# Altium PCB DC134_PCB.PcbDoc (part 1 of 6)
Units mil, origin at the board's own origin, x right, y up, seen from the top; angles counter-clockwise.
Board outline 4000 x 2750 mil, 6 copper layers (L1_Top Layer, L2_GND1, L3_Signal, L4_Plane, L5_GND2, L6_Bottom Layer), stack 57.7 mil thick; 399 components, 238 nets, 1523 pads, 671 vias.
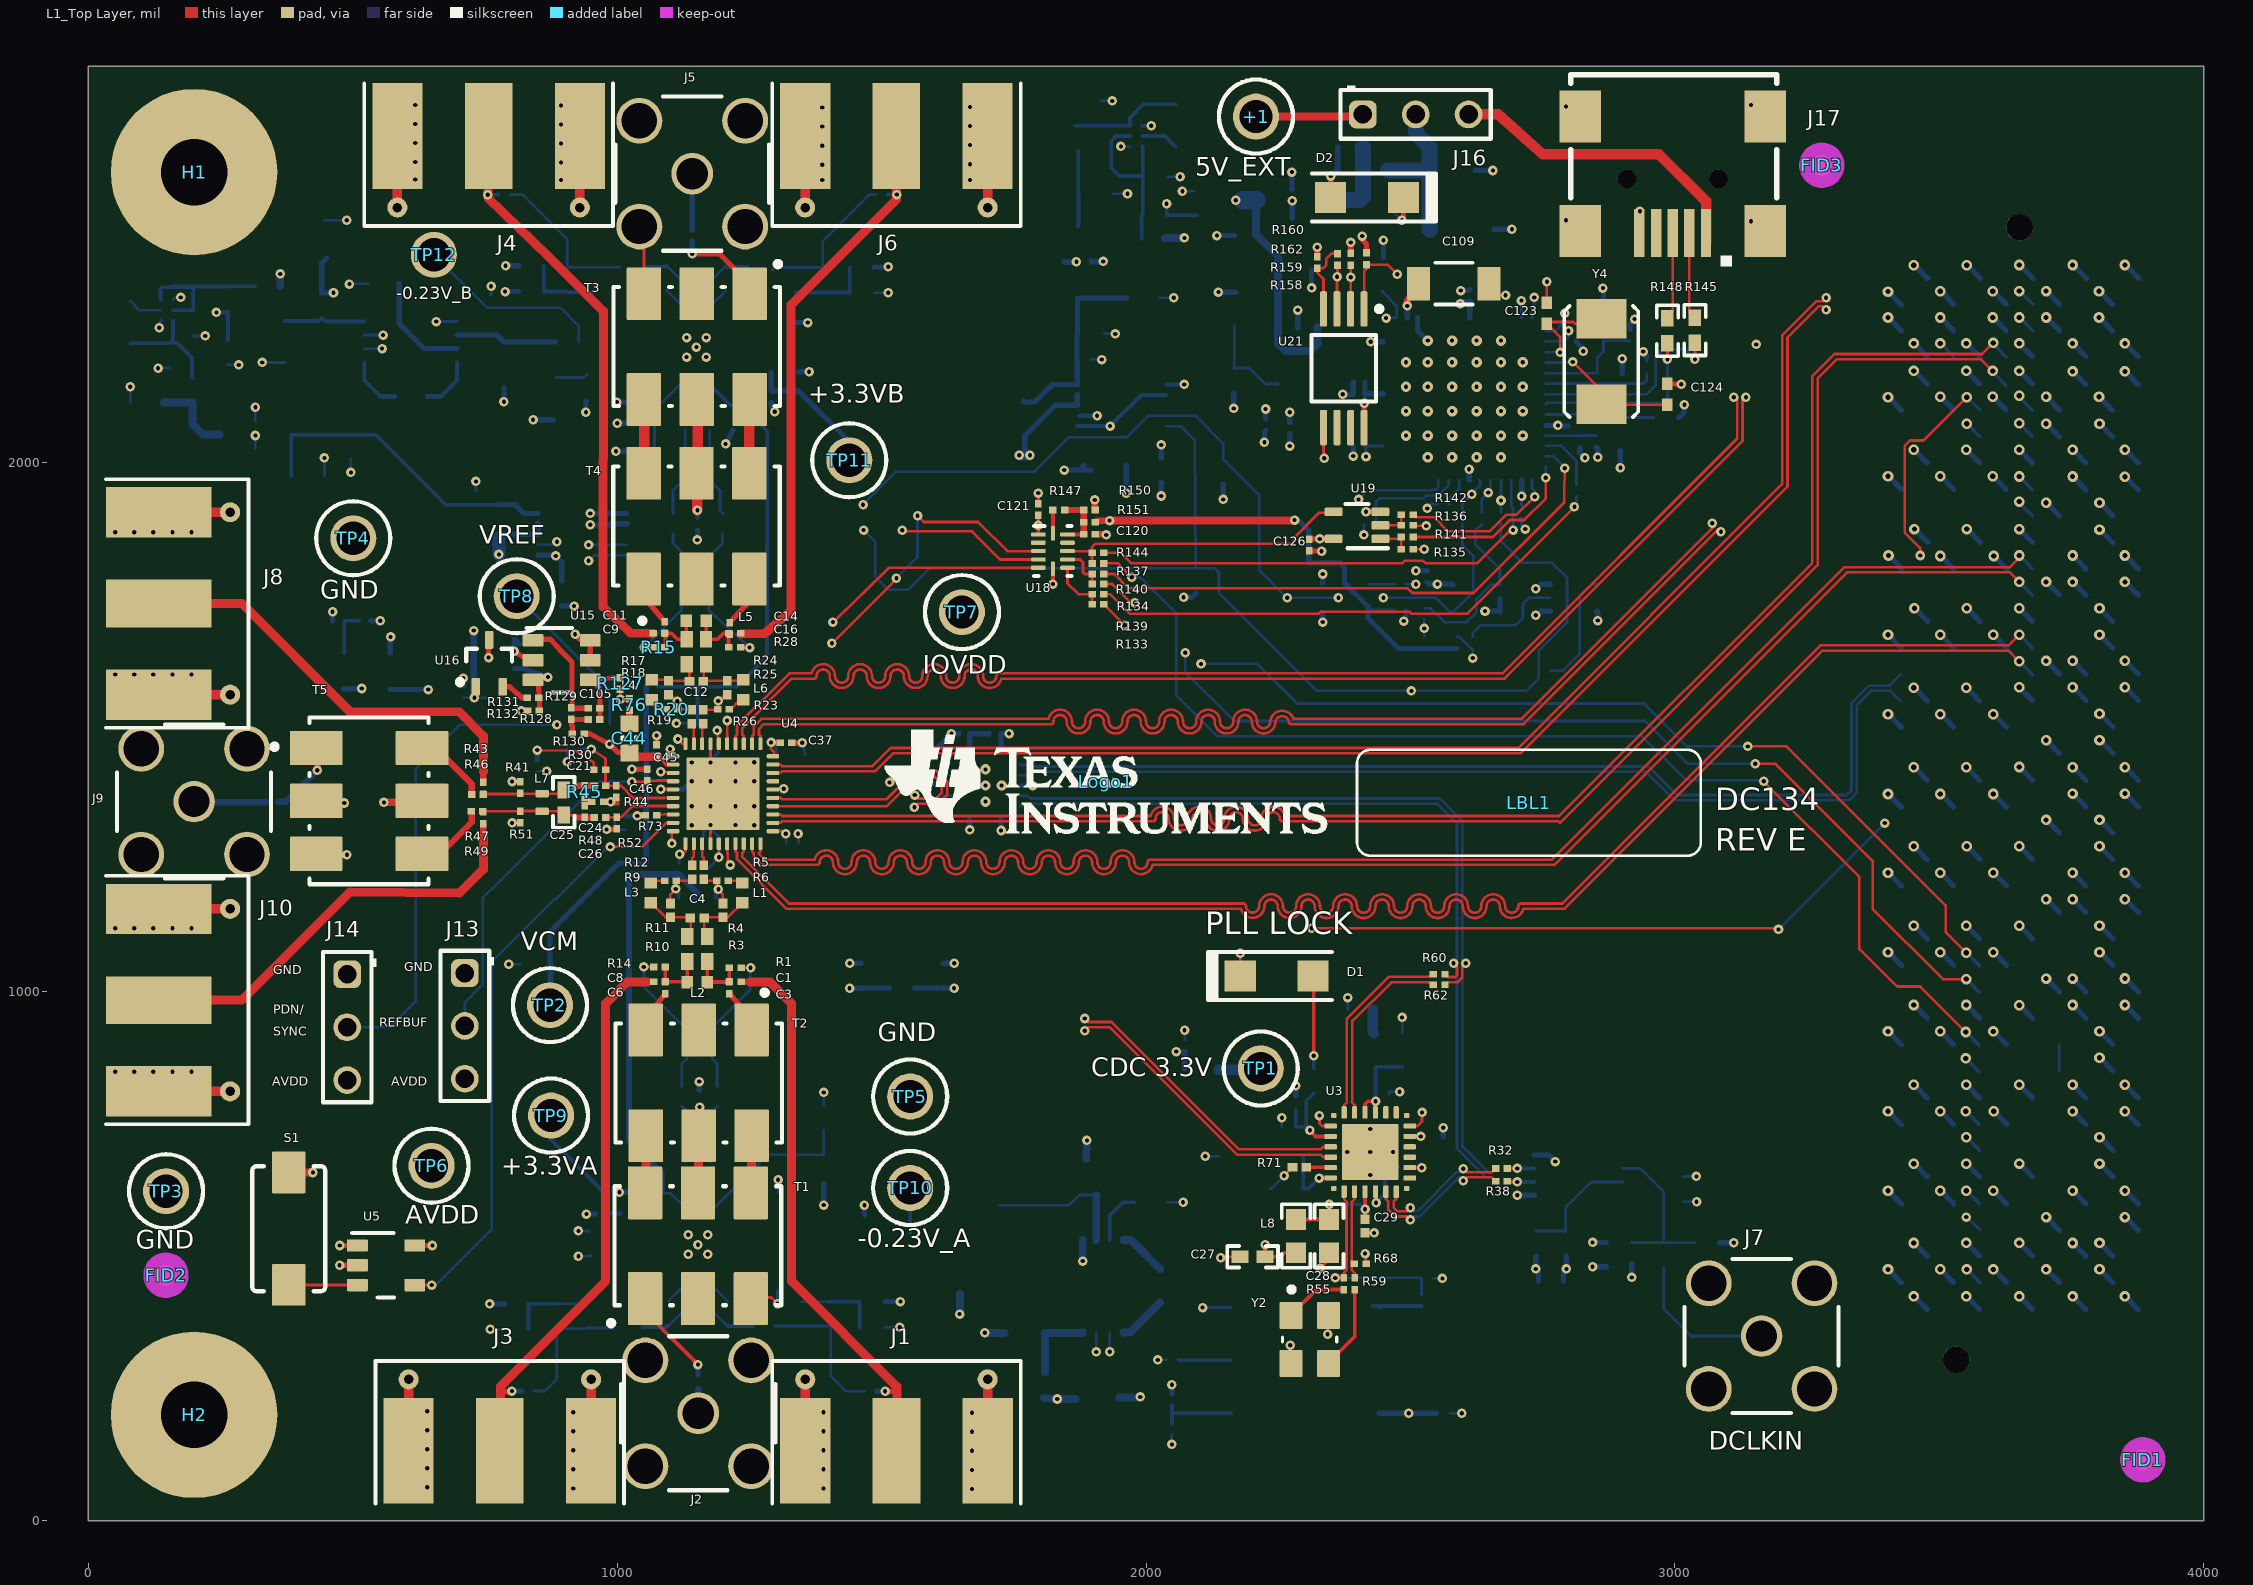
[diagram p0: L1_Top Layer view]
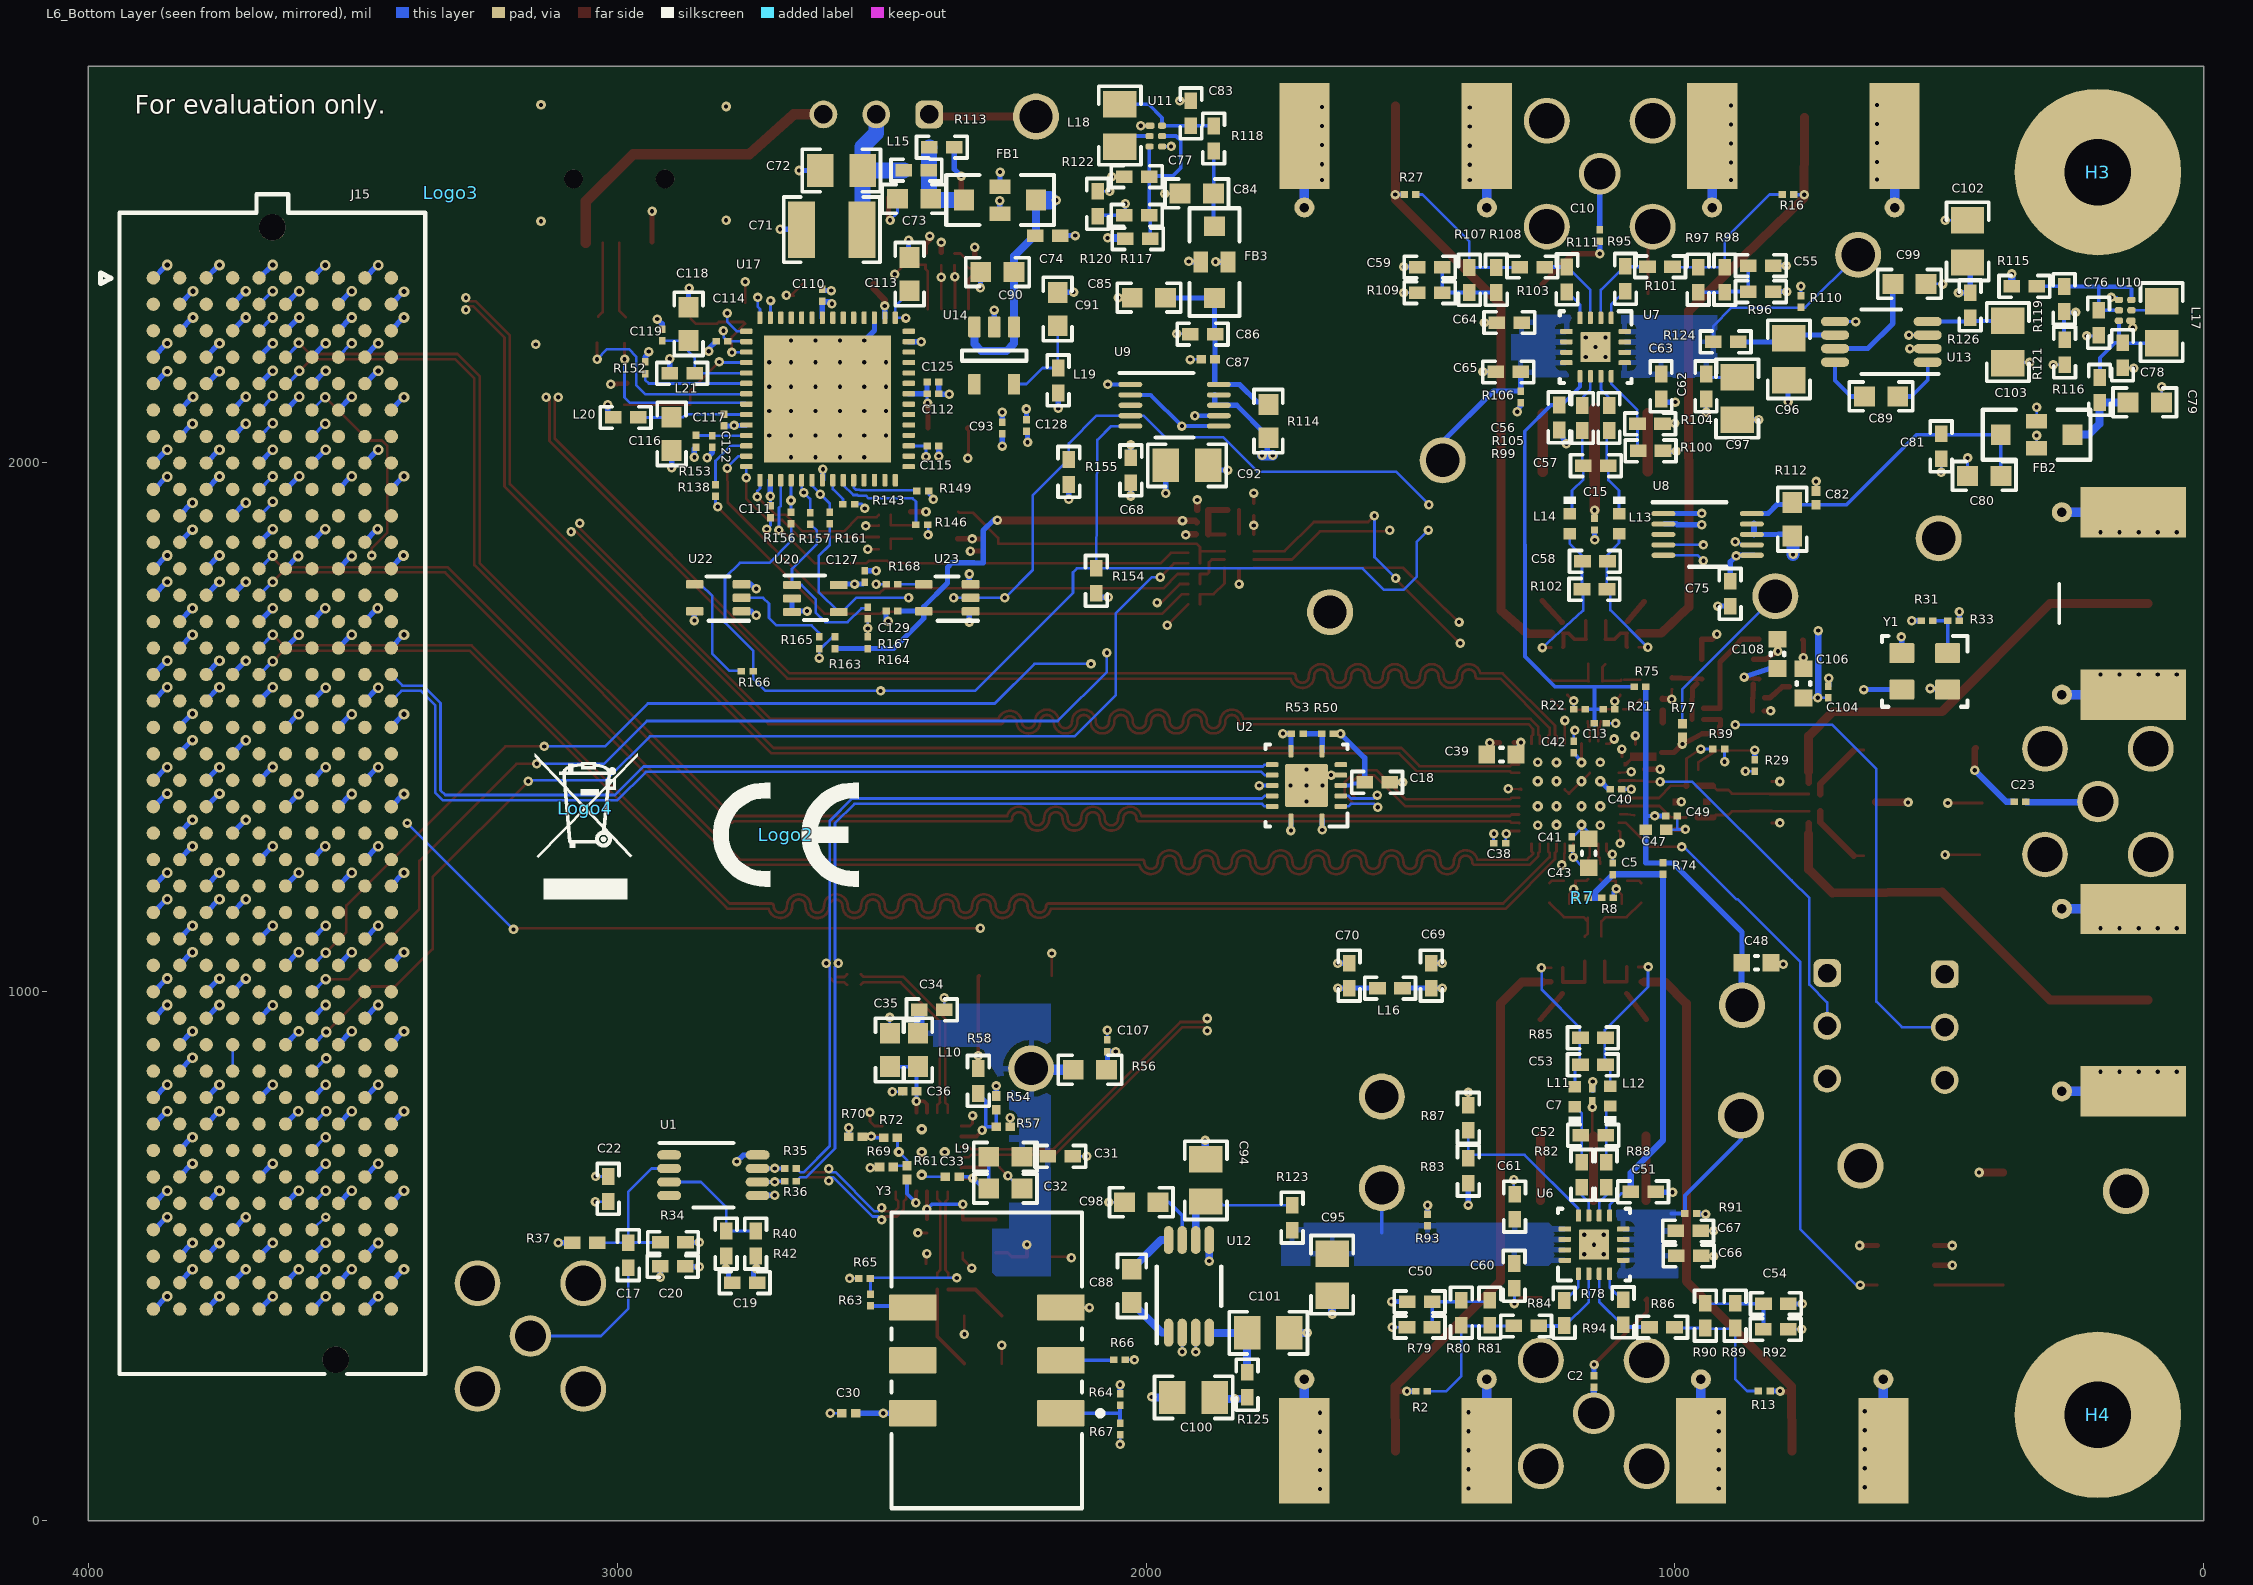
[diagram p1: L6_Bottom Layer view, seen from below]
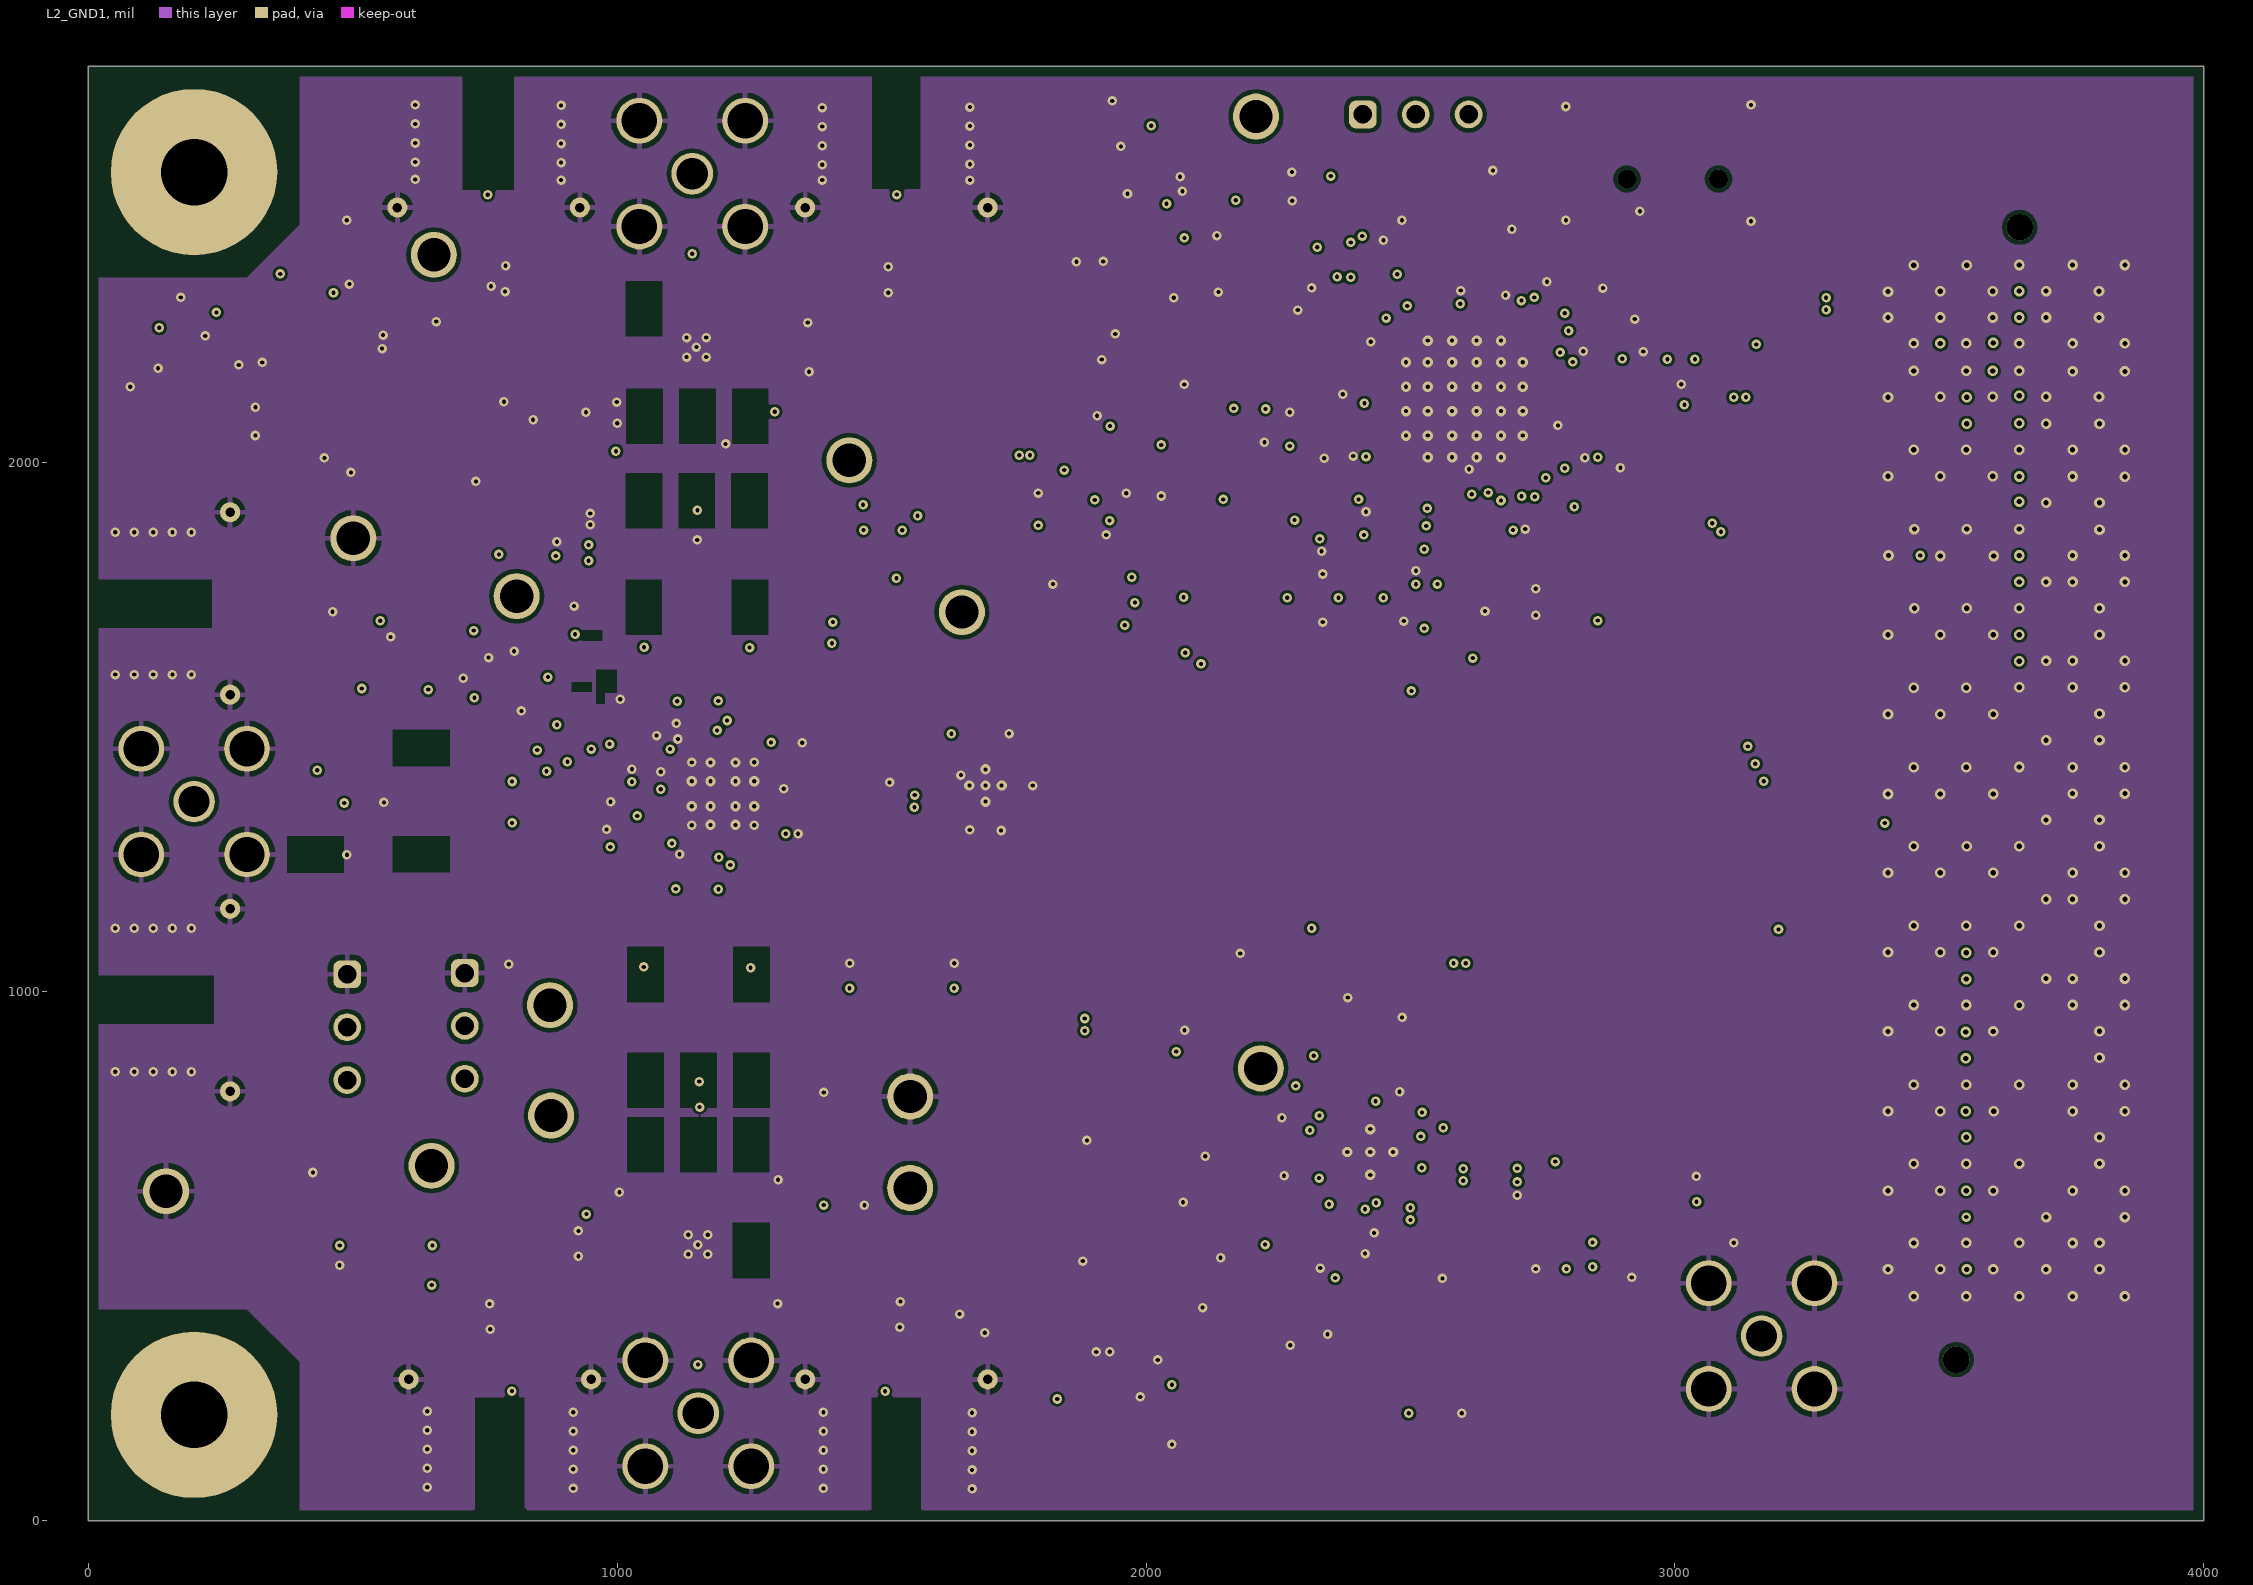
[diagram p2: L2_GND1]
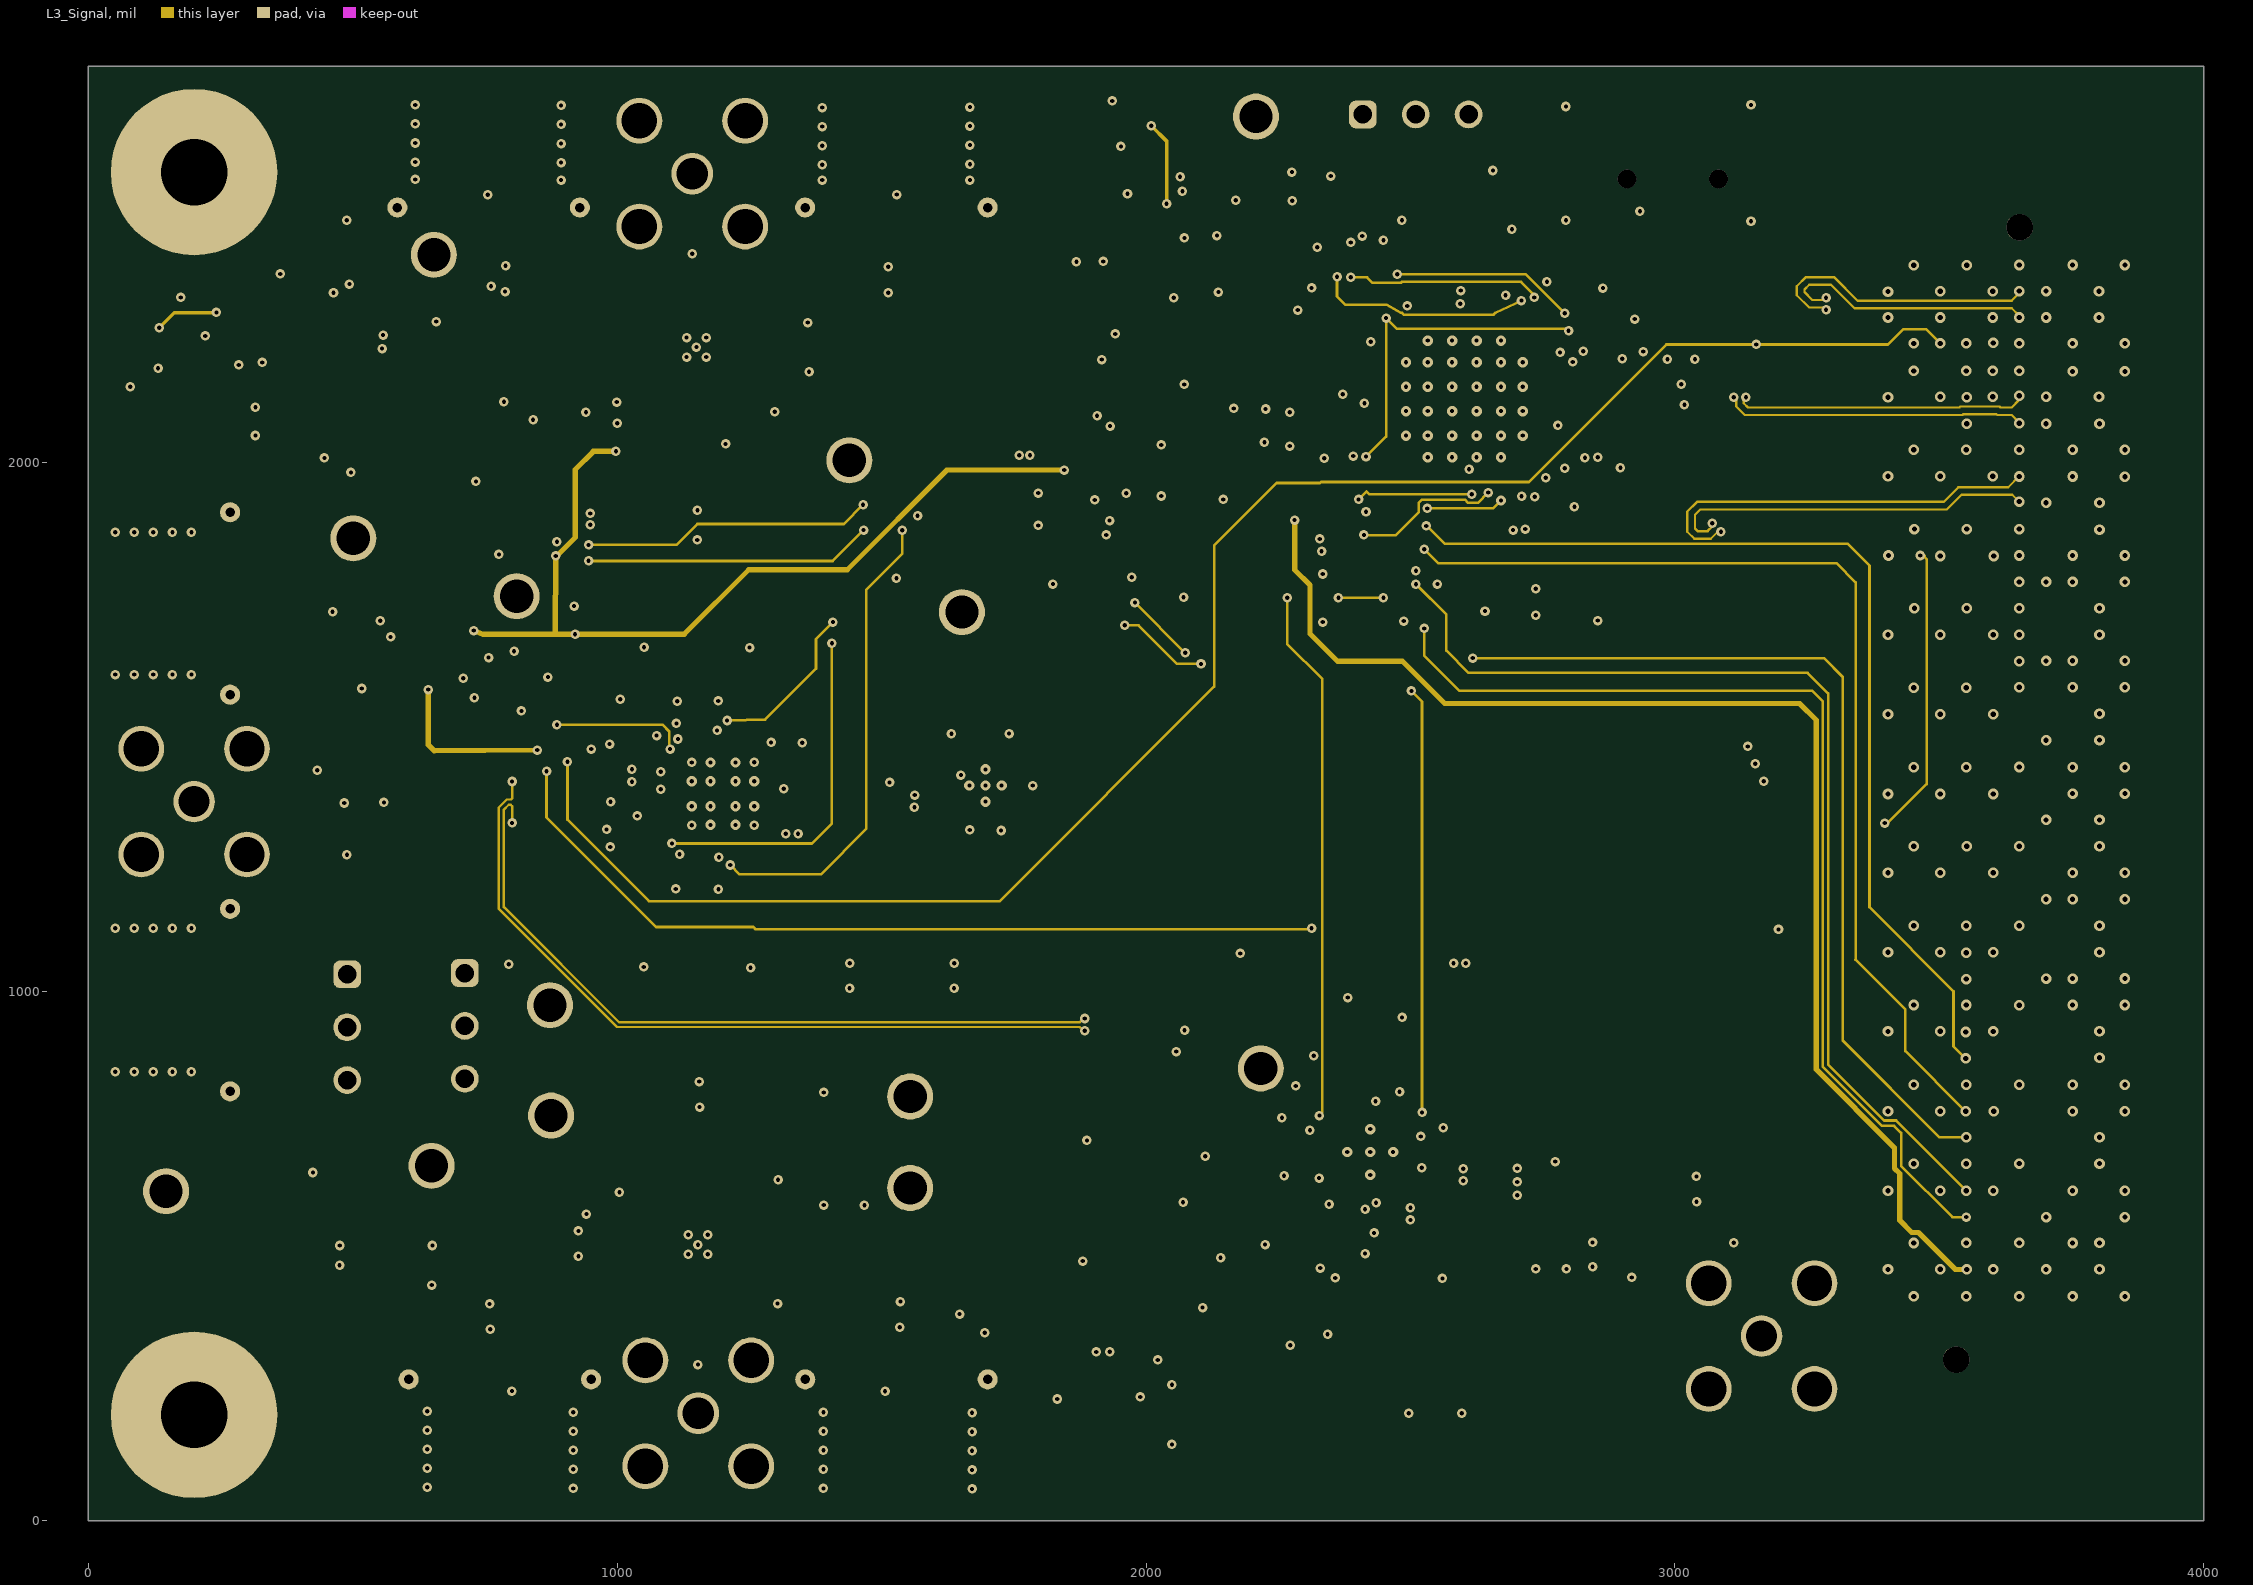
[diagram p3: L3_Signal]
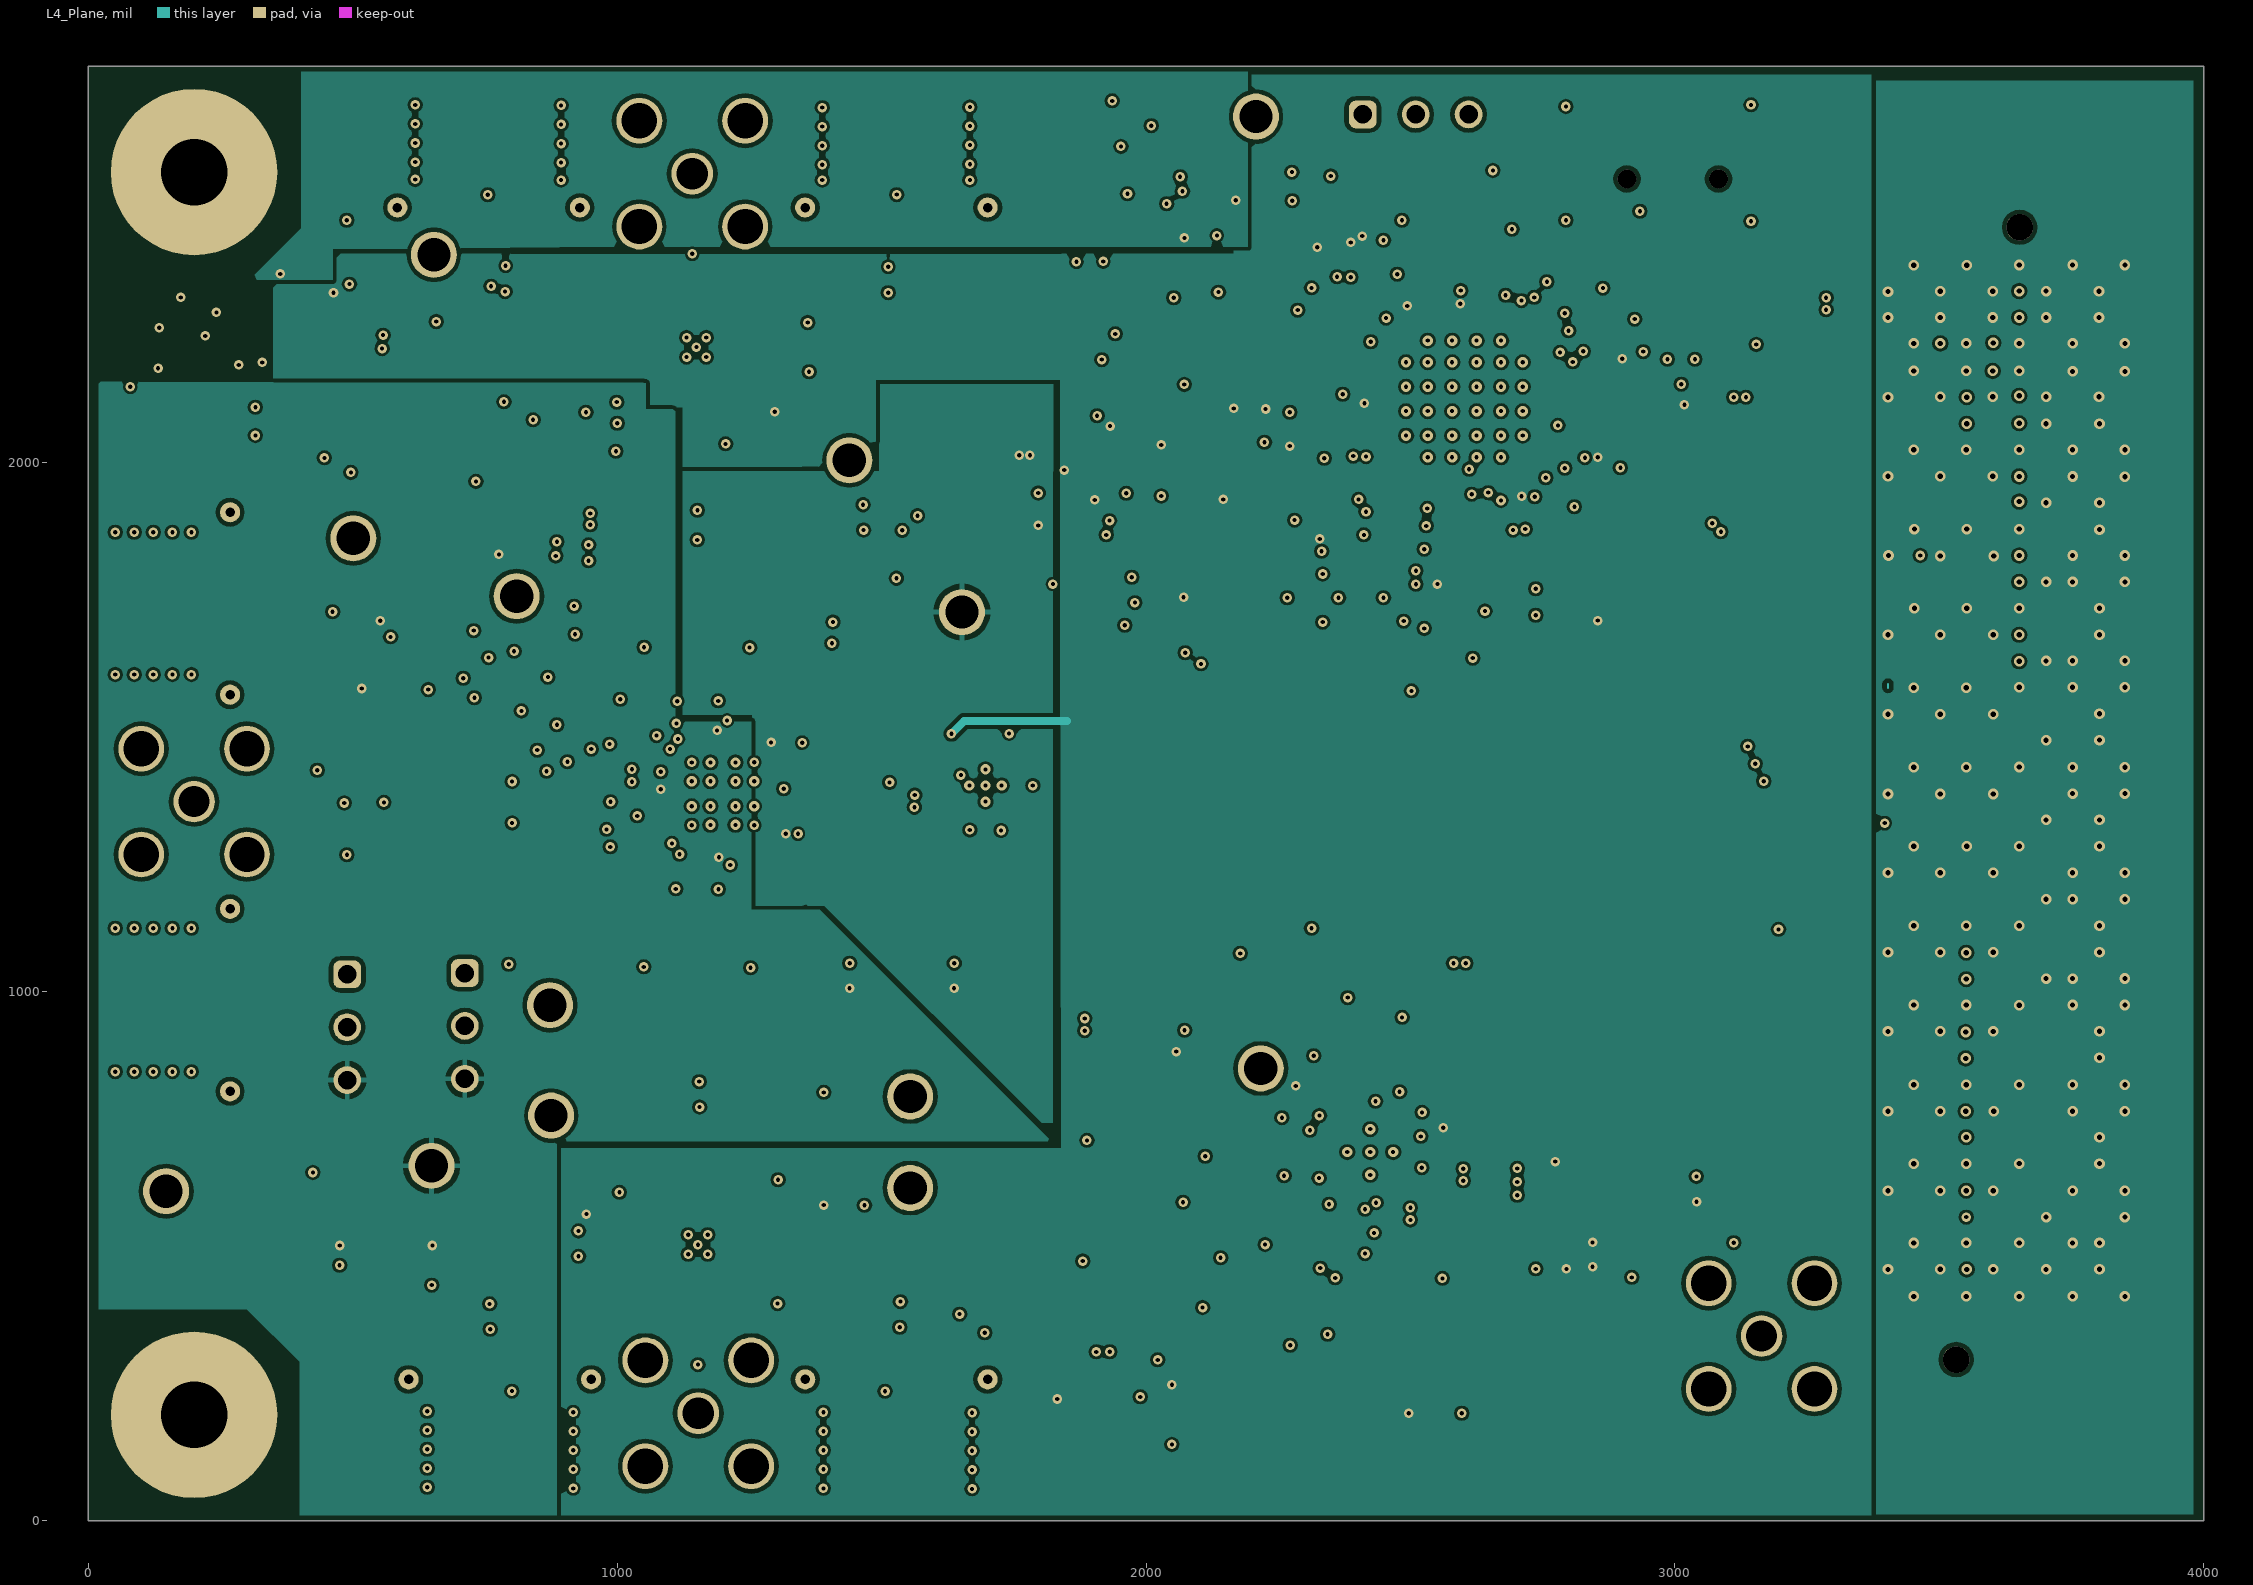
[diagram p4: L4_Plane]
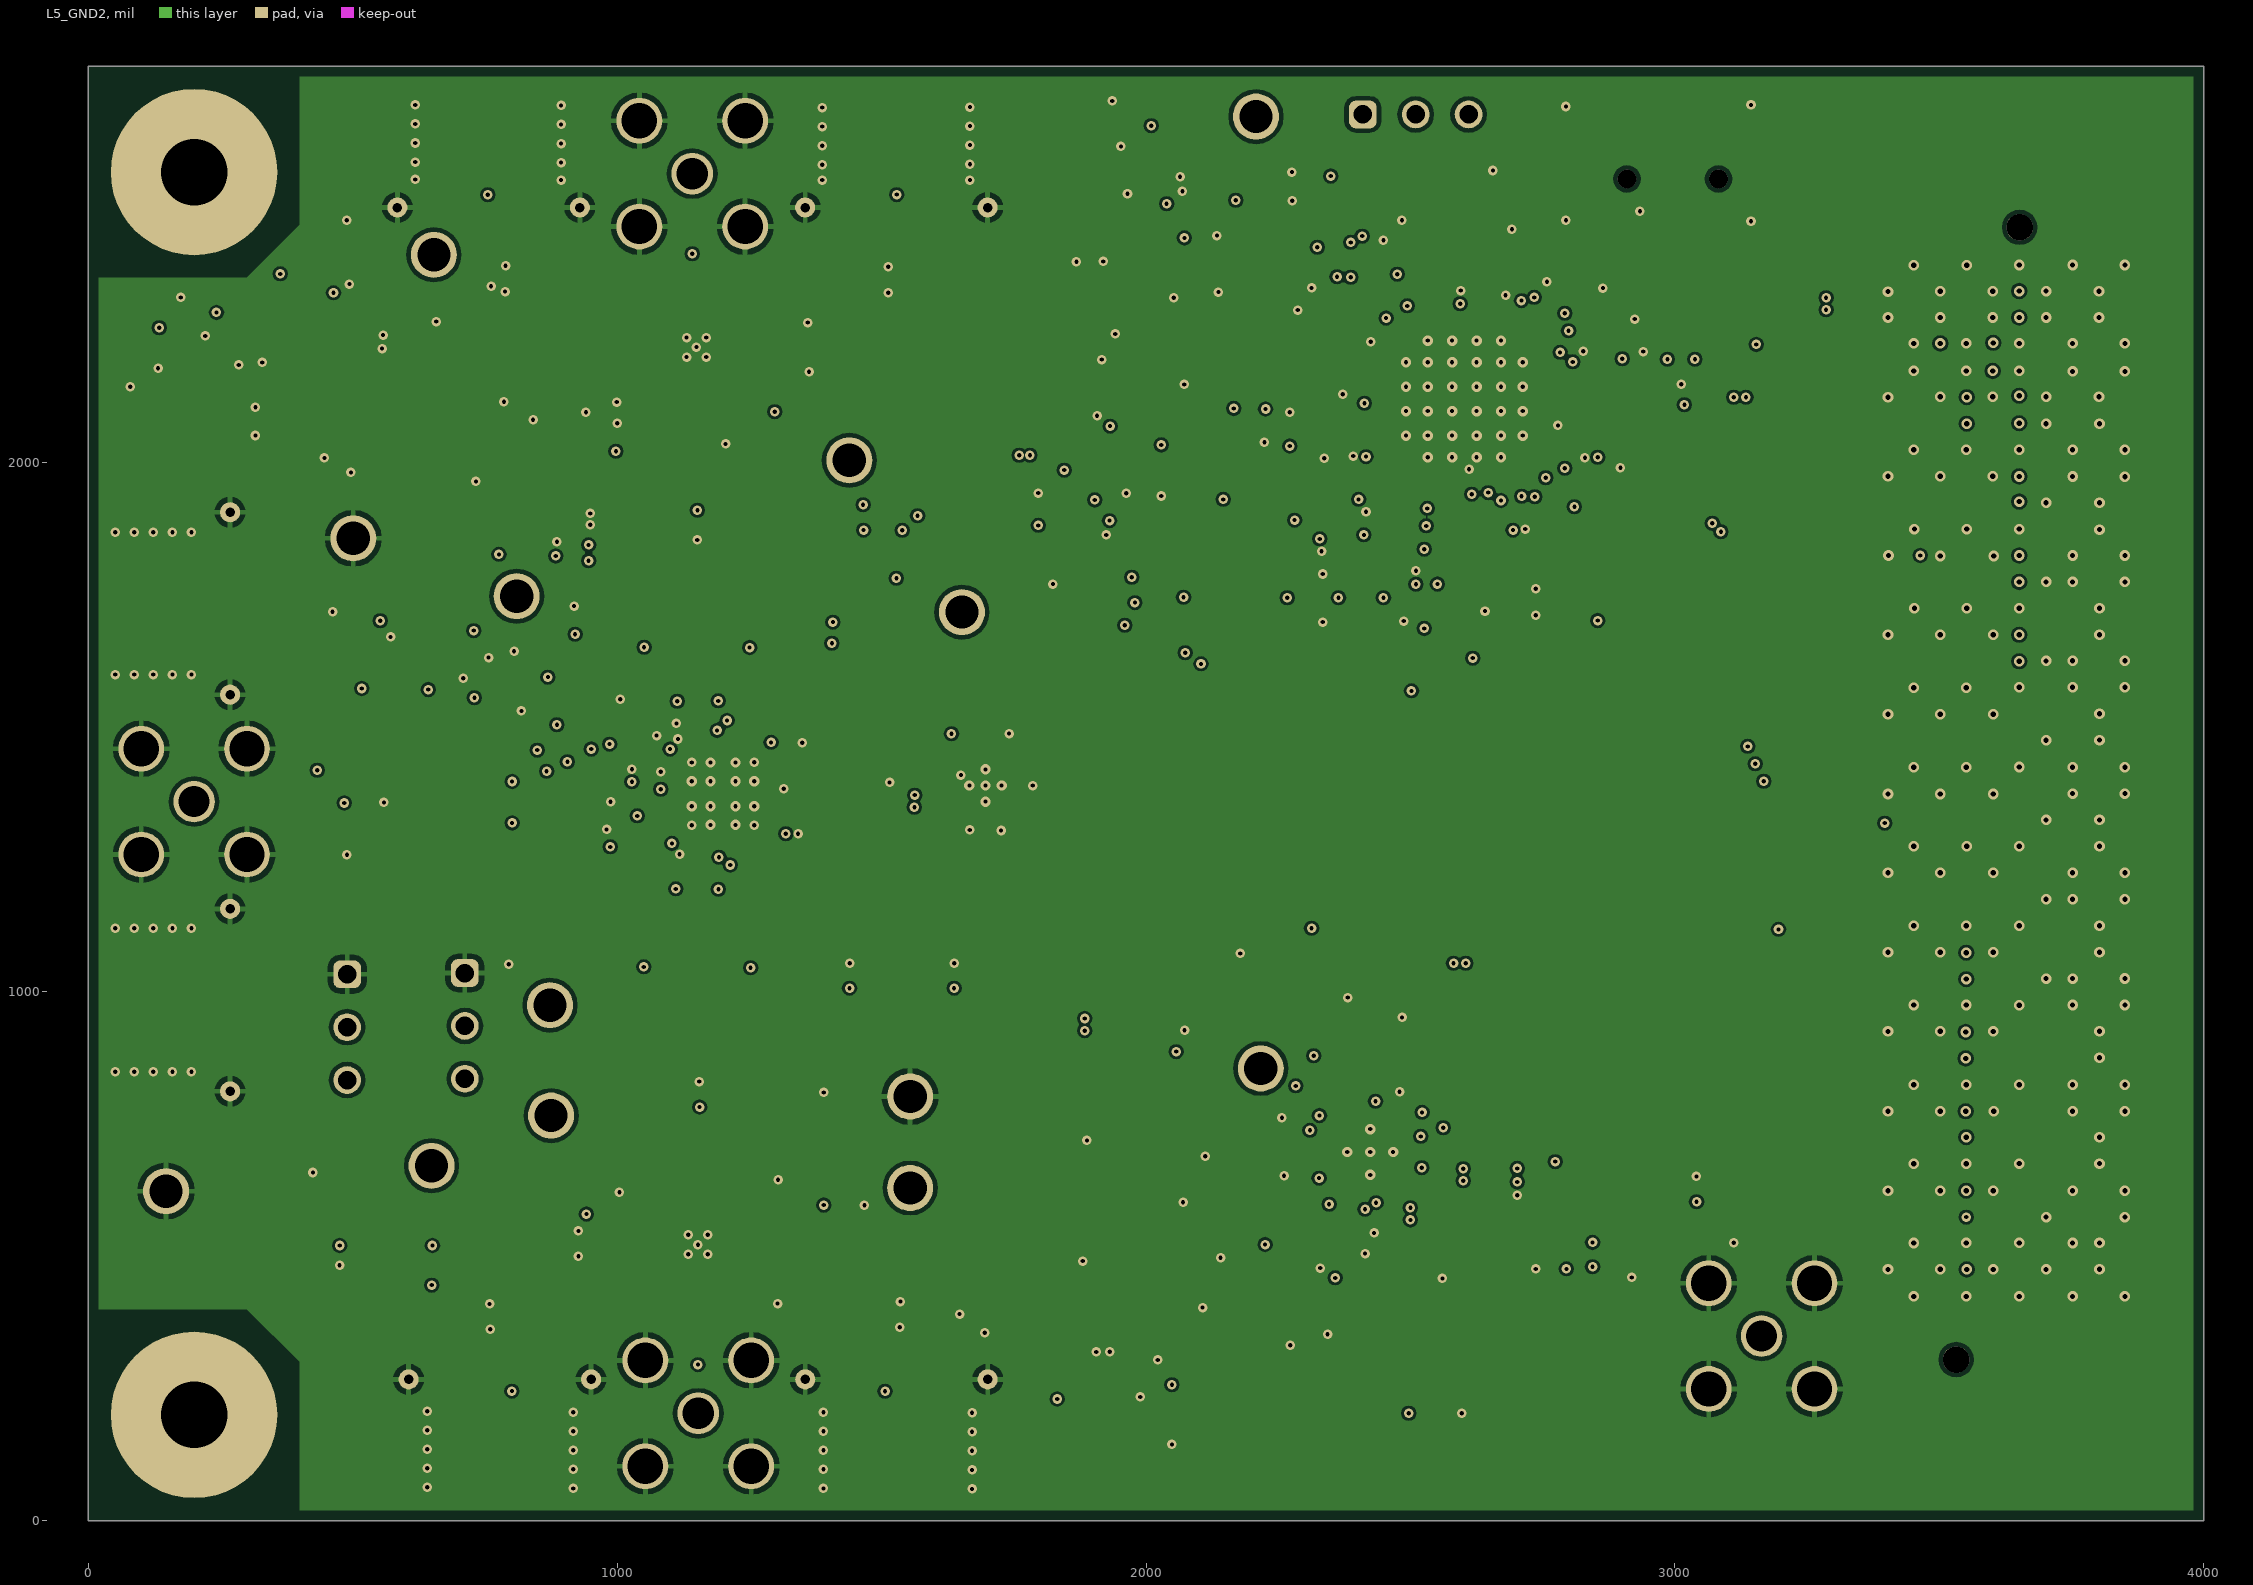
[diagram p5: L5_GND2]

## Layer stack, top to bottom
Top Solder: solder mask 0.5, Solder Resist, Dk 3.5
L1_Top Layer: signal copper 0.7
Dielectric 1: dielectric 8.5, Dk 4.7
L2_GND1: signal copper 0.7
Dielectric 2: dielectric 14, Dk 4.7
L3_Signal: signal copper 0.7
Dielectric 3: dielectric 8.5, Dk 4.7
L4_Plane: signal copper 0.7
Dielectric 4: dielectric 14, Dk 4.7
L5_GND2: signal copper 0.7
Dielectric 5: dielectric 8.5, Dk 4.7
L6_Bottom Layer: signal copper 0.7
Bottom Solder: solder mask 0.5, Solder Resist, Dk 3.5

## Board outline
0,0 4000,0 4000,2750 0,2750

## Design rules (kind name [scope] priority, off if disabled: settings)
AcuteAngle [All] p1: minimum=4.50000000000000E+0001 checktracksonly=FALSE
AssemblyTestPointUsage [All] p1: valid=2
BoardOutlineClearance BoardOutlineClearance_MountingHoles [OnCopper and InComponentClass('Mounting Holes')] p1: gap=40 ignorepadtopadclearanceinfootprint=FALSE except(50: Text-OutlineEdge Text-CavityEdge Text-CutoutEdge Text-SplitBarrior Text-SplitContinuation)
BoardOutlineClearance BoardOutlineClearance_Poly [OnCopper and IsPoly] p2: gap=10 ignorepadtopadclearanceinfootprint=FALSE
BoardOutlineClearance [OnCopper and Not InComponentClass('Logo') and not InComponentClass('FiducialMark') and not InPoly] p3: gap=30 ignorepadtopadclearanceinfootprint=FALSE
Clearance ClearanceVia [IsVia] p1: gap=5 ignorepadtopadclearanceinfootprint=TRUE
Clearance Clearance_FMC [WithinRoom('FMC')] p2: gap=5 ignorepadtopadclearanceinfootprint=FALSE except(0: Arc-Hole Track-Hole SMDPad-Hole THPad-Hole Via-Hole Fill-Hole Poly-Hole Region-Hole Text-Hole)
Clearance Clearance_Keepouts [((IsTrack Or IsArc) And Not InPoly) And IsFree and IsKeepOut vs ((IsTrack Or IsArc) And Not InPoly) And IsFree and IsKeepOut] p3: gap=5 ignorepadtopadclearanceinfootprint=FALSE except(0: Arc-Hole Track-Hole SMDPad-Hole THPad-Hole Via-Hole Fill-Hole Poly-Hole Region-Hole)
Clearance Clearance_FiducialMark [IsKeepOut and InComponentClass('FiducialMark') vs IsPad and InComponentClass('FiducialMark')] p4: gap=0 ignorepadtopadclearanceinfootprint=FALSE
Clearance ClearancePlane [InPoly] p5: gap=8 ignorepadtopadclearanceinfootprint=TRUE
Clearance [All] p6: gap=5 ignorepadtopadclearanceinfootprint=TRUE
ComponentClearance "ComponentClearance_Pad Share" [InComponent('R1', 'R4', 'C30', 'C7', 'R13') vs InComponent('R7', 'R59', 'C32', 'C22', 'R82')] p1: gap=0 collisioncheckmode=3 verticalgap=0 showdistances=FALSE
ComponentClearance ComponentClearance_MountingHoles_FiducialMarks [InComponentClass('Mounting Holes') vs InComponentClass('FiducialMark')] p2: gap=10 collisioncheckmode=3 verticalgap=10 showdistances=FALSE
ComponentClearance ComponentClearance_Shunt [InComponentClass('Header') vs InComponentClass('Shunt')] p3: gap=0 collisioncheckmode=3 verticalgap=0 showdistances=FALSE
ComponentClearance ComponentClearance_Logo [InComponentClass('Logo')] p4: gap=50 collisioncheckmode=3 verticalgap=10 showdistances=FALSE
ComponentClearance ComponentClearance_ScrewToNut [(HasFootprint('NY PMS 440 0025 PH')) vs (HasFootprint('Keystone_1902C'))] p5: gap=5 collisioncheckmode=3 verticalgap=10 showdistances=FALSE
ComponentClearance ComponentClearance_MountingHoles [InComponentClass('Mounting Holes')] p6: gap=10 collisioncheckmode=3 verticalgap=100000 showdistances=FALSE
ComponentClearance ComponentClearance_SmallPassives [HasFootprint('0201*') or HasFootprint('0402*') or HasFootprint('0508') or HasFootprint('0603*') or HasFootprint('0612') or HasFootprint('0805*') or HasFootprint('0815*') or HasFootprint('0830*') or HasFootprint('1206*') or HasFootprint('1210*') or HasFootprint('1808*') or HasFootprint('1812*') or HasFootprint('1825*') or HasFootprint('2010*') or HasFootprint('2220*') or HasFootprint('2225*') or HasFootprint('2512*') or HasFootprint('2728*') or HasFootprint('3518*') or HasFootprint('LQG15WZ_02') vs HasFootprint('0201*') or HasFootprint('0402*') or HasFootprint('0508') or HasFootprint('0603*') or HasFootprint('0612') or HasFootprint('0805*') or HasFootprint('0815*') or HasFootprint('0830*') or HasFootprint('1206*') or HasFootprint('1210*') or HasFootprint('1808*') or HasFootprint('1812*') or HasFootprint('1825*') or HasFootprint('2010*') or HasFootprint('2220*') or HasFootprint('2225*') or HasFootprint('2512*') or HasFootprint('2728*') or HasFootprint('3518*') or HasFootprint('LQG15WZ_02')] p7: gap=5 collisioncheckmode=3 verticalgap=10 showdistances=FALSE
ComponentClearance ComponentClearance_THtoSMT [IsThruComponent vs IsSMTComponent] p8: gap=5 collisioncheckmode=3 verticalgap=30 showdistances=FALSE
ComponentClearance ComponentClearance_THtoTH [IsThruComponent vs IsThruComponent] p9: gap=5 collisioncheckmode=3 verticalgap=30 showdistances=FALSE
ComponentClearance [All] p10: gap=5 collisioncheckmode=3 verticalgap=10 showdistances=FALSE
DiffPairsRouting DiffPairsRouting_2 [InDifferentialPairClass('OutputFMCPairs')] p1: maxlimit=10 minlimit=4.75 mostfreqgap=5 toplayer_mingap=5 toplayer_maxgap=5 toplayer_minwidth=5 toplayer_maxwidth=5 toplayer_prefwidth=5 midlayer5_mingap=5 midlayer5_maxgap=5 midlayer5_minwidth=4.4 midlayer5_maxwidth=4.4 midlayer5_prefwidth=4.4 midlayer6_maxgap=4.75 midlayer6_prefgap=4.75 midlayer6_minwidth=4.4 midlayer6_maxwidth=4.4 midlayer6_prefwidth=4.4 midlayer7_mingap=10 midlayer7_prefgap=10 midlayer7_minwidth=15 midlayer7_maxwidth=15 midlayer7_prefwidth=15 midlayer8_mingap=10 midlayer8_prefgap=10 midlayer8_minwidth=15 midlayer8_maxwidth=15 midlayer8_prefwidth=15 bottomlayer_mingap=5 bottomlayer_maxgap=5 bottomlayer_minwidth=5 bottomlayer_maxwidth=5 bottomlayer_prefwidth=5 maxuncoupledlength=500
DiffPairsRouting DiffPairs1 [All] p2: maxlimit=10 minlimit=4.75 mostfreqgap=5 toplayer_mingap=5 toplayer_maxgap=5 toplayer_minwidth=5 toplayer_maxwidth=5 toplayer_prefwidth=5 midlayer5_prefgap=10 midlayer5_minwidth=4.4 midlayer5_maxwidth=4.4 midlayer5_prefwidth=4.4 midlayer6_maxgap=4.75 midlayer6_prefgap=4.75 midlayer6_minwidth=4.4 midlayer6_maxwidth=4.4 midlayer6_prefwidth=4.4 midlayer7_mingap=5 midlayer7_maxgap=5 midlayer7_minwidth=5 midlayer7_maxwidth=5 midlayer7_prefwidth=5 midlayer8_mingap=5 midlayer8_maxgap=5 midlayer8_minwidth=5 midlayer8_maxwidth=5 midlayer8_prefwidth=5 bottomlayer_mingap=5 bottomlayer_maxgap=5 bottomlayer_minwidth=5 bottomlayer_maxwidth=5 bottomlayer_prefwidth=5 maxuncoupledlength=500
DiffPairsRouting DiffPair_DIFF90DiffPairsRouting [InDifferentialPairClass('DIFF90')] p3: maxlimit=12 minlimit=10 mostfreqgap=10 toplayer_mingap=12 toplayer_prefgap=12 toplayer_minwidth=12 toplayer_maxwidth=12 toplayer_prefwidth=12 midlayer5_maxgap=10 midlayer5_minwidth=15 midlayer5_maxwidth=15 midlayer5_prefwidth=15 midlayer6_maxgap=10 midlayer6_minwidth=15 midlayer6_maxwidth=15 midlayer6_prefwidth=15 midlayer7_maxgap=10 midlayer7_minwidth=15 midlayer7_maxwidth=15 midlayer7_prefwidth=15 midlayer8_maxgap=10 midlayer8_minwidth=15 midlayer8_maxwidth=15 midlayer8_prefwidth=15 bottomlayer_mingap=12 bottomlayer_prefgap=12 bottomlayer_minwidth=12 bottomlayer_maxwidth=12 bottomlayer_prefwidth=12 maxuncoupledlength=500
DiffPairsRouting [All] p4: maxlimit=100 minlimit=5 mostfreqgap=10 toplayer_maxgap=5 toplayer_prefgap=5 toplayer_minwidth=5 toplayer_maxwidth=5 toplayer_prefwidth=5 midlayer5_mingap=10 midlayer5_minwidth=15 midlayer5_maxwidth=15 midlayer5_prefwidth=15 midlayer6_mingap=10 midlayer6_minwidth=15 midlayer6_maxwidth=15 midlayer6_prefwidth=15 midlayer7_mingap=10 midlayer7_minwidth=15 midlayer7_maxwidth=15 midlayer7_prefwidth=15 midlayer8_mingap=10 midlayer8_minwidth=15 midlayer8_maxwidth=15 midlayer8_prefwidth=15 bottomlayer_maxgap=5 bottomlayer_prefgap=5 bottomlayer_minwidth=5 bottomlayer_maxwidth=5 bottomlayer_prefwidth=5 maxuncoupledlength=1000
FabricationTestPointUsage TestPointUsage [All] p1: valid=2 allowmultiple=FALSE
FabricationTestpoint Testpoint [All] p1: side=3 testpointundercomponent=TRUE minsize=40 maxsize=100 preferedsize=60 minholesize=0 maxholesize=40 preferedholesize=32 testpointgrid=1 allowsidetop=TRUE allowsidebottom=TRUE usegrid=TRUE gridtolerance=0.01
FanoutControl Fanout_LCC [IsLCC] p1: bgadir=Out bgaviamode=Centered fanoutstyle=Auto fanoutdirection=Alternating viagrid=1 // Fanout_LCC (Default Rule)
FanoutControl Fanout_BGA [IsBGA or WithinRoom('FMC')] p2: bgadir=Out bgaviamode=Centered fanoutstyle=BGA fanoutdirection=Alternating viagrid=1 // Fanout_BGA (Default Rule)
FanoutControl Fanout_Default [All] p4: bgadir=Out bgaviamode=Centered fanoutstyle=Auto fanoutdirection=Alternating viagrid=1 // Fanout_Default (Default Rule)
FanoutControl Fanout_Small [(CompPinCount < 5)] p5: bgadir=Out bgaviamode=Centered fanoutstyle=Auto fanoutdirection=OutThenIn viagrid=1 // Fanout_Small (Default Rule)
HoleSize [All] p1: absolutevalues=TRUE maxlimit=251 minlimit=7.87 maxpercent=80.000 minpercent=20.000
MatchedLengths [InNetClass('FMC Connections')] p1: tolerance=10 checknetsindiffpair=FALSE checkdiffpairvsdiffpair=TRUE checkxsignals=TRUE checkothers=TRUE
MatchedLengths SDA_SDIo [InDifferentialPair('DA0') and InDifferentialPair('DA1')] p2: tolerance=5 checknetsindiffpair=FALSE checkdiffpairvsdiffpair=TRUE checkxsignals=TRUE checkothers=TRUE
MatchedLengths Output [InDifferentialPair('DCLKIN_SMA')] p3: tolerance=5 checknetsindiffpair=FALSE checkdiffpairvsdiffpair=TRUE checkxsignals=TRUE checkothers=TRUE
MatchedLengths DiffPair_DIFF100MatchedLengths [InDifferentialPairClass('DIFF100')] p4: tolerance=5 checknetsindiffpair=TRUE checkdiffpairvsdiffpair=FALSE checkxsignals=FALSE checkothers=FALSE
MatchedLengths DiffPair_DIFF90MatchedLengths [InDifferentialPairClass('DIFF90')] p5: tolerance=5 checknetsindiffpair=TRUE checkdiffpairvsdiffpair=FALSE checkxsignals=FALSE checkothers=FALSE
MinimumAnnularRing MinimumAnnularRing_ThermalPadVias [IsVia and InAnyComponent] p1: minimumring=5
MinimumAnnularRing [All] p2: minimumring=5
MinimumSolderMaskSliver MinimumSolderMaskSliver_Logo [InComponentClass('Logo') vs InComponentClass('Logo')] p1: minsoldermaskwidth=0.7
MinimumSolderMaskSliver [All] p2: minsoldermaskwidth=3.74
PlaneClearance [All] p1: clearance=10
PlaneConnect [All] p1: planeconnectstyle=Direct reliefexpansion=5 reliefentries=4 reliefconductorwidth=5 reliefairgap=5
PolygonConnect ViaConnect [All vs IsVia] p1: connectstyle=Direct reliefconductorwidth=10 reliefentries=4 polygonreliefangle="90 Angle" airgapwidth=10
PolygonConnect GND_Thermal [All] p2: connectstyle=Relief reliefconductorwidth=10 reliefentries=4 polygonreliefangle="90 Angle" airgapwidth=10
RoutingVias RoutingVias_FMC [WithinRoom('FMC')] p1: holewidth=8 width=18 viastyle="Through Hole" minholewidth=8 minwidth=18 maxholewidth=8 maxwidth=18
RoutingVias ThermalPadVias [IsVia and InAnyComponent] p2: holewidth=7.87 width=19.68 viastyle="Through Hole" minholewidth=7.87 minwidth=19.68 maxholewidth=12.99 maxwidth=23.62
RoutingVias [All] p3: holewidth=8 width=18 viastyle="Through Hole" minholewidth=7.87 minwidth=18 maxholewidth=40 maxwidth=65
SilkToBoardRegionClearance [Not ((IsComment or IsDesignator) And (Hide <> 'False')) and not InRegion(1000,500,4000,800)] p1:
SilkToSilkClearance SilkToSilkClearance_Pb-FreeLogo [(HasFootprint('Pb-Free_Overlay_Medium') OR HasFootprint('Pb-Free_Overlay_Small')) vs (HasFootprint('Pb-Free_Overlay_Medium') OR HasFootprint('Pb-Free_Overlay_Small'))] p1: silktosilkclearance=0
SilkToSilkClearance [All] p2: silktosilkclearance=3
SilkToSolderMaskClearance SilkToComponentPadClearance [(IsPad or IsFill or IsRegion) and InAnycomponent] p1: minsilkscreentomaskgap=3.2 clearancetoexposedcopper=TRUE
SilkToSolderMaskClearance "Silk to Solder Mask Opening" [All] p2: minsilkscreentomaskgap=4 clearancetoexposedcopper=FALSE
SolderMaskExpansion [All] p1: expansion=1.97
Width Width_FMC [WithinRoom('FMC')] p1: maxlimit=5 minlimit=5 preferedwidth=5
Width [All] p2: maxlimit=100 minlimit=5 preferedwidth=5 checkconnectedcopper=TRUE
14 further rules are at their usual default settings.

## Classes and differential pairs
component class DC134_FDA: C50 C51 C52 C53 C54 C55 C56 C57 C58 C59 C60 C61 C62 C63 C64 C65 C66 C67 L11 L12 L13 L14 R78 R79 R80 R81 R82 R83 R84 R85 R86 R87 R88 R89 R90 R91 R92 R93 R94 R95 R96 R97 R98 R99 R100 R101 R102 R103 R104 R105 R106 R107 R108 R109 R110 R111 TP9 TP10 TP11 TP12 U6 U7
component class Label: LBL1
component class Header: J13 J14 J16
component class DC134_AIN: C1 C2 C3 C4 C5 C6 C7 C8 C9 C10 C11 C12 C13 C14 C15 C16 J1 J2 J3 J4 J5 J6 L1 L2 L3 L4 L5 L6 R1 R2 R3 R4 R5 R6 R7 R8 R9 R10 R11 R12 R13 R14 R15 R16 R17 R18 R19 R20 R21 R22 R23 R24 R25 R26 R27 R28 T1 T2 T3 T4
component class DC134_Power: +1 C68 C69 C70 C71 C72 C73 C74 C75 C76 C77 C78 C79 C80 C81 C82 C83 C84 C85 C86 C87 C88 C89 C90 C91 C92 C93 C94 C95 C96 C97 C98 C99 C100 C101 C102 C103 D2 FB1 FB2 FB3 FB4 J16 J18 L15 L16 L17 L18 L19 R112 R113 R114 R115 R116 R117 R118 R119 R120 R121 R122 R123 R124 R125 R126 R171 R172 R173 R174 R175 R176 U8 U9 U10 U11 U12 U13 U14
component class DC134_FMC: J15
component class DC134_Device: C37 C38 C39 C40 C41 C42 C43 C44 C45 C46 C47 C48 C49 J13 J14 R73 R74 R75 R76 R77 S1 TP2 TP3 TP4 TP5 TP6 TP7 TP8 U4 U5
component class DC134_CLK: C17 C18 C19 C20 C21 C22 C23 C24 C25 C26 C27 C28 C29 C30 C31 C32 C33 C34 C35 C36 D1 J7 J8 J9 J10 L7 L8 L9 L10 R29 R30 R31 R32 R33 R34 R35 R36 R37 R38 R39 R40 R41 R42 R43 R44 R45 R46 R47 R48 R49 R50 R51 R52 R53 R54 R55 R56 R57 R58 R59 R60 R61 R62 R63 R64 R65 R66 R67 R68 R69 R70 R71 R72 T5 TP1 U1 U2 U3 Y1 Y2 Y3
component class "Mounting Holes": H1 H2
component class Logo: Logo1
component class DC134_Hardware: FID1 FID2 FID3 H1 H2 H3 H4 LBL1 Logo1 Logo2 Logo3 Logo4 ZZ1 ZZ2 ZZ3
component class FiducialMark: FID1 FID2 FID3
component class AssemblyNote: ZZ1 ZZ2 ZZ3
component class DC134_USB: C109 C110 C111 C112 C113 C114 C115 C116 C117 C118 C119 C120 C121 C122 C123 C124 C125 C126 C127 C128 C129 J17 L20 L21 R133 R134 R135 R136 R137 R138 R139 R140 R141 R142 R143 R144 R145 R146 R147 R148 R149 R150 R151 R152 R153 R154 R155 R156 R157 R158 R159 R160 R161 R162 R163 R164 R165 R166 R167 R168 U17 U18 U19 U20 U21 U22 U23 Y4
component class DC134_Reference: C104 C105 C106 C107 C108 R127 R128 R129 R130 R131 R132 U15 U16
differential pair DCLKIN_CDC: +DCLKIN_CDC_P -DCLKIN_CDC_N
differential pair SECREF: +SECREF_P -SECREF_N
differential pair InternalCLK: +InternalCLK_P -InternalCLK_N
differential pair AMP_CHB_OUT: +AMP_CHB_OUT_P -AMP_CHB_OUT_N
differential pair AMP_CHB_IN: +AMP_CHB_IN_P -AMP_CHB_IN_N
differential pair AMP_CHA_OUT: +AMP_CHA_OUT_P -AMP_CHA_OUT_N
differential pair AMP_CHA_IN: +AMP_CHA_IN_P -AMP_CHA_IN_N
differential pair DCLKIN_SMA: +DCLKIN_SMA_P -DCLKIN_SMA_N
differential pair FCLK: +FCLK_P -FCLK_N
differential pair DCLK: +DCLK_P -DCLK_N
differential pair DCLKIN: +DCLKIN_P -DCLKIN_N
differential pair DCLKIN_FPGA: +DCLKIN_FPGA_P -DCLKIN_FPGA_N
differential pair DB1: +DB1_P -DB1_N
differential pair DB0: +DB0_P -DB0_N
differential pair DA1: +DA1_P -DA1_N
differential pair DA0: +DA0_P -DA0_N
differential pair BIN: +BIN_P -BIN_N
differential pair SMA_CLK: +SMA_CLK_P -SMA_CLK_N
differential pair AIN: +AIN_P -AIN_N
differential pair CLK: +CLK_P -CLK_N

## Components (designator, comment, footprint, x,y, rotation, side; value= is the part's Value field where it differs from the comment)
+1 "5011" Keystone5011 2208,2655 r90 top
C1 "GRM033Z71C104KE14D" 0201L 1223.26,1018.77 r180 top value=0.1uF
C2 "GRM033Z71C104KE14D" 0201L 1152.87,263.02 r90 bottom value=0.1uF
C3 "GRM033Z71C104KE14D" 0201L 1212.24,1007.74 r90 top value=0.1uF
C4 "GRM033R71E101KA01D" 0201 1151.5,1139.5 r180 top value=100pF
C5 "GRM033Z71C104KE14D" 0201L 1117.28,1232.5 r270 bottom value=0.1uF
C6 "GRM033Z71C104KE14D" 0201L 1091.24,1007.74 r90 top value=0.1uF
C7 "GRM033Z71C104KE14D" 0201L 1155.87,805.24 r270 bottom value=0.1uF
C8 "GRM033Z71C104KE14D" 0201L 1079.93,1018.72 r0 top value=0.1uF
C9 "GRM033Z71C104KE14D" 0201L 1079.06,1677.95 r0 top value=0.1uF
C10 "GRM033Z71C104KE14D" 0201L 1142,2430.08 r270 bottom value=0.1uF
C11 "GRM033Z71C104KE14D" 0201L 1090.09,1688.98 r270 top value=0.1uF
C12 "GRM033R71E101KA01D" 0201 1149.85,1587.05 r0 top value=100pF
C13 "GRM033Z71C104KE14D" 0201L 1140.94,1507.5 r0 bottom value=0.1uF
C14 "GRM033Z71C104KE14D" 0201L 1213,1687 r270 top value=0.1uF
C15 "GRM033Z71C104KE14D" 0201L 1151.79,1884.23 r90 bottom value=0.1uF
C16 "GRM033Z71C104KE14D" 0201L 1222.39,1677.95 r180 top value=0.1uF
C17 "GRM155R61E104KA87D" 0402 2979,502 r270 bottom value=0.1uF
C18 "GRM155R61E104KA87D" 0402 1563,1396 r0 bottom value=0.1uF
C19 "GRM155R61E104KA87D" 0402 2759,450 r0 bottom value=0.1uF
C20 "GRM155R61E104KA87D" 0402 2895,481 r180 bottom value=0.1uF
C21 "GRM033Z71C104KE14D" 0201L 967.44,1389.67 r0 top value=0.1uF
C22 "GRM155R61E104KA87D" 0402 3017,627.15 r270 bottom value=0.1uF
C23 "GRM033Z71C104KE14D" 0201L 347.64,1359.3 r0 bottom value=0.1uF
C24 "GRM033Z71C104KE14D" 0201L 963.44,1359.65 r180 top value=0.1uF
C25 "GRM1555C1E390JA01D" 0402 899,1358 r270 top value=39pF
C26 "GRM033Z71C104KE14D" 0201L 967.44,1329.63 r0 top value=0.1uF
C27 "GRM152R60J105ME15D" 0402 2201.5,499 r180 top value=1uF
C28 "GRM188R61E475KE11D" 0603 2346.26,538 r270 top value=4.7uF
C29 "GRM033R61E104KE14J" 0201_033 2414.16,557 r270 top value=0.1uF
C30 "GRM033R61E104KE14J" 0201_033 2562,203 r0 bottom value=0.1uF
C31 "GRM152R60J105ME15D" 0402 2162,689 r180 bottom value=1uF
C32 "GRM188R61E475KE11D" 0603 2265.94,628 r180 bottom value=4.7uF
C33 "GRM033R61E104KE14J" 0201_033 2366.5,650.15 r0 bottom value=0.1uF
C34 "GRM152R60J105ME15D" 0402 2405,966 r180 bottom value=1uF
C35 "GRM188R61E475KE11D" 0603 2484.32,890 r90 bottom value=4.7uF
C36 "GRM033R61E104KE14J" 0201_033 2447,811.75 r0 bottom value=0.1uF
C37 "GRM033Z71C104KE14D" 0201L 1319,1471 r0 top value=0.1uF
C38 "GRM033Z71C104KE14D" 0201L 1331,1281 r0 bottom value=0.1uF
C39 "GRM188Z71A106MA73D" 0603L 1327.87,1448.56 r0 bottom value=10uF
C40 "GRM033Z71C104KE14D" 0201L 1111,1383 r0 bottom value=0.1uF
C41 "GRM033Z71C104KE14D" 0201L 1195,1282 r90 bottom value=0.1uF
C42 "GRM033Z71C104KE14D" 0201L 1191,1463 r270 bottom value=0.1uF
C43 "GRM188Z71A106MA73D" 0603L 1163,1262 r90 bottom value=10uF
C44 "GRM188Z71A106MA73D" 0603L 1023.33,1479 r90 top value=10uF
C45 "GRM033Z71C104KE14D" 0201L 1074.5,1456.5 r90 top value=0.1uF
C46 "GRM033Z71C104KE14D" 0201L 1057,1410 r90 top value=0.1uF
C47 "GRM155R70J105MA12D" 0402L 1035.5,1306.29 r180 bottom value=1uF
C48 "GRM188Z71A106MA73D" 0603L 845.62,1055 r180 bottom value=10uF
C49 "GRM033Z71C104KE14D" 0201L 1006.5,1332.5 r180 bottom value=0.1uF
C50 "GRM155R61E104KA87D" 0402 1482.62,413.87 r180 bottom value=0.1uF
C51 "GRM155R61E104KA87D" 0402 1059.87,621.74 r0 bottom value=0.1uF
C52 "GRM1555C1E330JA01D" 0402 1154.24,728.74 r180 bottom value=33pF
C53 "GRM1555C1H181JA01D" 0402 1154.87,861.84 r180 bottom value=180pF
C54 "GRM155R61E104KA87D" 0402 808.87,410.37 r180 bottom value=0.1uF
C55 "GRM155R61E104KA87D" 0402 837.5,2373 r0 bottom value=0.1uF
C56 "GRM155R61E104KA87D" 0402 1219,2086 r90 bottom value=0.1uF
C57 "GRM1555C1E330JA01D" 0402 1149.37,1995 r0 bottom value=33pF
C58 "GRM1555C1H181JA01D" 0402 1151.07,1814 r0 bottom value=180pF
C59 "GRM155R61E104KA87D" 0402 1463.5,2370.12 r0 bottom value=0.1uF
C60 "GRM155R61E104KA87D" 0402 1303.87,462.74 r270 bottom value=0.1uF
C61 "GRM155R61E104KA87D" 0402 1302.87,593.74 r90 bottom value=0.1uF
C62 "GRM155R61E104KA87D" 0402 941,2144.58 r270 bottom value=0.1uF
C63 "GRM155R61E104KA87D" 0402 1026.09,2144.58 r270 bottom value=0.1uF
C64 "GRM155R61E104KA87D" 0402 1313,2265.5 r0 bottom value=0.1uF
C65 "GRM155R61E104KA87D" 0402 1315,2172 r0 bottom value=0.1uF
C66 "GRM155R61E104KA87D" 0402 973.87,500.74 r180 bottom value=0.1uF
C67 "GRM155R61E104KA87D" 0402 974.87,547.74 r180 bottom value=0.1uF
C68 "GRM155R61E104KA87D" 0402 2028.5,1986 r270 bottom value=0.1uF
C69 "GRM152R60J105ME15D" 0402 1460.5,1030.5 r90 bottom value=1uF
C70 "GRM152R60J105ME15D" 0402 1616,1030.5 r90 bottom value=1uF
C71 "GRM32ER61A476KE20L" 1210_270 2594,2441 r0 bottom value=47uF
C72 "JMK212BJ226MG-T" 0805_HV 2576,2553 r0 bottom value=22uF
C73 "GRM188R61A106ME69D" 0603 2438.5,2499.5 r0 bottom value=10uF
C74 "GRM152R60J105ME15D" 0402 2186,2430 r180 bottom value=1uF
C75 "GRM155R61E104KA87D" 0402 895.5,1752.5 r270 bottom value=0.1uF
C76 "GRM155R60J225ME15D" 0402 198.5,2265.13 r270 bottom value=2.2uF
C77 "GRM155R60J225ME15D" 0402 2017.51,2541.21 r0 bottom value=2.2uF
C78 "GRM155R60J475ME87D" 0402_065 153.5,2203.63 r270 bottom value=4.7uF
C79 "GRM188R61A106ME69D" 0603 111.5,2114.5 r180 bottom value=10uF
C80 "GRM188R61A106ME69D" 0603 415,1975.5 r0 bottom value=10uF
C81 "GRM152R60J105ME15D" 0402 496.5,2031.5 r270 bottom value=1uF
C82 "GRM033R61E104KE14J" 0201_033 733,1934 r90 bottom value=0.1uF
C83 "GRM155R60J475ME87D" 0402_065 1914.97,2660.94 r90 bottom value=4.7uF
C84 "GRM188R61A106ME69D" 0603 1903.94,2509.56 r0 bottom value=10uF
C85 "GRM188R61A106ME69D" 0603 1994.5,2312.5 r0 bottom value=10uF
C86 "GRM152R60J105ME15D" 0402 1893,2243.5 r0 bottom value=1uF
C87 "GRM033R61E104KE14J" 0201_033 1882.5,2196 r0 bottom value=0.1uF
C88 "GRM188R60J475KE19D" 0603 2026.78,444 r90 bottom value=4.7uF
C89 "GRM188R60J475KE19D" 0603 610,2125.72 r0 bottom value=4.7uF
C90 "885012206052" 0603 2281,2361 r0 bottom value=1uF
C91 "885012206052" 0603 2167,2291 r90 bottom value=1uF
C92 "885012207026" 0805_HV 1922.5,1995.5 r0 bottom value=10uF
C93 "GRM033Z71C104KE14D" 0201L 2272.09,2066 r270 bottom value=0.1uF
C94 "JMK212BJ226MG-T" 0805_HV 1887,643.5 r90 bottom value=22uF
C95 "885012207026" 0805_HV 1648,465 r270 bottom value=10uF
C96 "JMK212BJ226MG-T" 0805_HV 784.5,2196 r270 bottom value=22uF
C97 "885012207026" 0805_HV 882,2121.88 r270 bottom value=10uF
C98 "GRM188R60J475KE19D" 0603 2009,602 r0 bottom value=4.7uF
C99 "GRM188R60J475KE19D" 0603 556.3,2338.61 r180 bottom value=4.7uF
C100 "885012207026" 0805_HV 1910,233 r0 bottom value=10uF
C101 "885012207026" 0805_HV 1768.78,355 r180 bottom value=10uF
C102 "885012207026" 0805_HV 446.5,2419.06 r90 bottom value=10uF
C103 "885012207026" 0805_HV 370.5,2228.5 r270 bottom value=10uF
C104 "GRM033Z71C104KE14D" 0201L 709.78,1567 r90 bottom value=0.1uF
C105 "GRM033R71E101JA01D" 0201_033L 956.5,1536 r0 top value=100pF
C106 "GRM188Z71A106MA73D" 0603L 756.78,1583 r90 bottom value=10uF
C107 "GRM033Z71C104KE14D" 0201L 2073,898 r90 bottom value=0.1uF
C108 "GRM188Z71A106MA73D" 0603L 806,1639 r90 bottom value=10uF
C109 "C3216X5R0J107M160AB" 1206_190 2582,2339 r0 top value=100uF
C110 "GRM033Z71C104KE14D" 0201L 2612,2317 r270 bottom value=0.1uF
C111 "GRM033Z71C104KE14D" 0201L 2710,1907.59 r90 bottom value=0.1uF
C112 "GRM033Z71C104KE14D" 0201L 2403,2131 r0 bottom value=0.1uF
C113 "C1608X5R1E335K080AC" 0603 2447,2357 r90 bottom value=3.3uF
C114 "GRM033Z71C104KE14D" 0201L 2802,2230 r180 bottom value=0.1uF
C115 "GRM033Z71C104KE14D" 0201L 2403,2032 r0 bottom value=0.1uF
C116 "GRM188Z71C475KE21D" 0603 2897,2055 r270 bottom value=4.7uF
C117 "GRM033Z71C104KE14D" 0201L 2798,2081 r90 bottom value=0.1uF
C118 "GRM188Z71C475KE21D" 0603 2865,2263 r90 bottom value=4.7uF
C119 "GRM033Z71C104KE14D" 0201L 2915,2242 r270 bottom value=0.1uF
C120 "GRM033Z71C104KE14D" 0201L 1893,1865 r0 top value=0.1uF
C121 "GRM033Z71C104KE14D" 0201L 1796.24,1912 r90 top value=0.1uF
C122 "CC0201JRNPO8BN101" 0201L 2820,2040.38 r270 bottom value=100pF
C123 "C1005C0G1H180J050BA" 0402L 2758,2283 r90 top value=18pF
C124 "C1005C0G1H180J050BA" 0402L 2986,2130 r90 top value=18pF
C125 "GRM033Z71C104KE14D" 0201L 2403,2153.12 r0 bottom value=0.1uF
C126 "GRM033Z71C104KE14D" 0201L 2308.59,1845 r270 top value=0.1uF
C127 "GRM033Z71C104KE14D" 0201L 2532,1785 r90 bottom value=0.1uF
C128 "GRM033Z71C104KE14D" 0201L 2226,2071 r270 bottom value=0.1uF
C129 "GRM033Z71C104KE14D" 0201L 2480,1720 r0 bottom value=0.1uF
D1 "LTST-C150KGKT" LTST-C150_1206_Green 2247,1030 r0 top value=Green
D2 "LTST-C150KGKT" LTST-C150_1206_Green 2418,2502 r180 top value=Green
FB1 "NFM31PC276B0J3L" Murata_NFM31P 2276,2497 r180 bottom value="27 uF"
FB2 "NFM31PC276B0J3L" Murata_NFM31P 316,2053.4 r0 bottom value="27 uF"
FB3 "NFM31PC276B0J3L" Murata_NFM31P 1870.5,2379.79 r270 bottom value="27 uF"
FID1 "Fiducial" Fiducial10-20 3885,115 r0 top
FID2 "Fiducial" Fiducial10-20 147,464 r0 top
FID3 "Fiducial" Fiducial10-20 3278,2563 r0 top
H1 "NY PMS 440 0025 PH" "NY PMS 440 0025 PH" 200,2550 r0 top
H2 "NY PMS 440 0025 PH" "NY PMS 440 0025 PH" 200,200 r0 top
H3 "1902E" Keystone_1902E 200,2550 r180 bottom locked
H4 "1902E" Keystone_1902E 200,200 r180 bottom locked
J1 "142-0701-801" Johnson_142-0701-801#1 1528.13,132 r180 top
J2 "901-144-8RFX" AMPHENOL_901-144-8RFX 1153.37,203 r90 top
J3 "142-0701-801" Johnson_142-0701-801#1 778.13,132 r180 top
J4 "142-0701-801" Johnson_142-0701-801#1 757,2618 r0 top
J5 "901-144-8RFX" AMPHENOL_901-144-8RFX 1142,2547 r0 top
J6 "142-0701-801" Johnson_142-0701-801#1 1528,2618 r0 top
J7 "901-144-8RFX" AMPHENOL_901-144-8RFX 3164,349 r0 top
J8 "142-0701-801" Johnson_142-0701-801#2 133,1734.25 r90 top
J9 "901-144-8RFX" AMPHENOL_901-144-8RFX 200,1359.65 r90 top
J10 "142-0701-801" Johnson_142-0701-801#1 133,984.25 r90 top
J13 "87224-3" TE_87224-3 712,935.5 r270 top
J14 "87224-3" TE_87224-3 489.5,933 r270 top
J15 "ASP-134488-01" Samtec_ASP-134488-01 3652,1375 r180 bottom
J16 "87224-3" TE_87224-3 2510,2659 r0 top
J17 "1734035-2" CONN_USB-Mini-B-1734035-2 2996,2537 r180 top
L1 "LQG15HSR18J02D" IND_LQG15H 1237,1187 r90 top value=180nH
L2 "LQG15HSR18J02D" IND_LQG15H 1151.5,1018.5 r0 top value=180nH
L3 "LQG15HSR18J02D" IND_LQG15H 1063.79,1187 r90 top value=180nH
L4 "LQG15HSR18J02D" IND_LQG15H 1065.55,1571 r270 top value=180nH
L5 "LQG15HSR18J02D" IND_LQG15H 1149.5,1701.45 r180 top value=180nH
L6 "LQG15HSR18J02D" IND_LQG15H 1238.42,1571 r270 top value=180nH
L7 "LQG15WZ43NG02D" LQG15WZ_02 858,1358 r90 top value=43nH
L8 "BLM18KG121TH1D" 0603 2283.89,538 r90 top value="120 ohm"
L9 "BLM18KG121TH1D" 0603 2265.94,688 r0 bottom value="120 ohm"
L10 "BLM18KG121TH1D" 0603 2431.2,890 r270 bottom value="120 ohm"
L11 "LQG15HSR22J02D" IND_LQG15H 1189.43,801.74 r90 bottom value=220nH
L12 "LQG15HSR22J02D" IND_LQG15H 1122.38,802.74 r90 bottom value=220nH
L13 "LQG15HSR22J02D" IND_LQG15H 1105.47,1885 r270 bottom value=220nH
L14 "LQG15HSR22J02D" IND_LQG15H 1199.04,1885 r270 bottom value=220nH
L15 "74279271" 0402 2434.17,2553.5 r180 bottom value="120 ohm"
L16 "74279271" 0402 1538.5,1007 r0 bottom value="120 ohm"
L17 "LQM21PN1R0MC0D" 0805_HV 79.5,2266.13 r270 bottom value=1uH
L18 "LQM21PN1R0MC0D" 0805_HV 2049.5,2638.09 r90 bottom value=1uH
L19 "74279271" 0402 2166,2156 r270 bottom value="120 ohm"
L20 "74279271" 0402 2984,2086 r180 bottom value="120 ohm"
L21 "74279271" 0402 2877,2169.5 r180 bottom value="120 ohm"
LBL1 "THT-14-423-10" Label_650x200 2724,1357.38 r0 top
Logo1 "Texas Instruments" TI_Stacked_Overlay_Small 1924,1397 r0 top
Logo2 "CE Mark" CE_Mark_5mm 2681,1297 r180 bottom
Logo3 "FCC disclaimer" FCC_disclaimer 3315,2511 r180 bottom
Logo4 "WEEE logo" WEEE_Minimum 3060,1347 r180 bottom
R1 "CRCW02010000Z0ED" 0201L 1223.24,1045.5 r180 top value=0
R2 "CRCW02010000Z0ED" 0201L 1479.22,244.5 r0 bottom value=0
R3 "RC0402JR-070RL" 0402 1170.5,1081 r90 top value=0
R4 "RC0201FR-7D33RL" 0201 1200,1154 r90 top value=33.0
R5 "RC0201FR-7D10RL" 0201 1163.85,1226 r90 top value=10.0
R6 "CRCW02010000Z0ED" 0201L 1199,1210 r180 top value=0
R7 "RC0201FR-0725R5L" 0201L 1175.19,1178.08 r0 bottom value=25.5
R8 "RC0201FR-0725R5L" 0201L 1127.5,1178.08 r0 bottom value=25.5
R9 "CRCW02010000Z0ED" 0201L 1101,1210 r0 top value=0
R10 "RC0402JR-070RL" 0402 1132.5,1081 r90 top value=0
R11 "RC0201FR-7D33RL" 0201 1100.69,1154 r90 top value=33.0
R12 "RC0201FR-7D10RL" 0201 1142,1226 r90 top value=10.0
R13 "CRCW02010000Z0ED" 0201L 830.99,245 r180 bottom value=0
R14 "CRCW02010000Z0ED" 0201L 1079.93,1047 r0 top value=0
R15 "CRCW02010000Z0ED" 0201L 1079.06,1651.5 r0 top value=0
R16 "CRCW02010000Z0ED" 0201L 785.75,2507.5 r180 bottom value=0
R17 "RC0402JR-070RL" 0402 1131.29,1643 r270 top value=0
R18 "RC0201FR-7D33RL" 0201 1097,1575 r270 top value=33.0
R19 "RC0201FR-7D10RL" 0201 1141,1520 r270 top value=10.0
R20 "CRCW02010000Z0ED" 0201L 1103.5,1534 r0 top value=0
R21 "RC0201FR-0725R5L" 0201L 1124.8,1534 r180 bottom value=25.5
R22 "RC0201FR-0725R5L" 0201L 1180.05,1534.5 r180 bottom value=25.5
R23 "CRCW02010000Z0ED" 0201L 1201,1534 r180 top value=0
R24 "RC0402JR-070RL" 0402 1168,1643 r270 top value=0
R25 "RC0201FR-7D33RL" 0201 1208,1575 r270 top value=33.0
R26 "RC0201FR-7D10RL" 0201 1163,1520 r270 top value=10.0
R27 "CRCW02010000Z0ED" 0201L 1500.5,2507.5 r0 bottom value=0
R28 "CRCW02010000Z0ED" 0201L 1222.39,1651.5 r180 top value=0
R29 "RC0201FR-7D49R9L" 0201L 849.15,1428 r270 bottom value=49.9
R30 "RC0201FR-7D49R9L" 0201L 967,1420 r0 top value=49.9
R31 "CRCW02010000Z0ED" 0201L 522.98,1701.52 r0 bottom value=0
R32 "CRCW02010000Z0ED" 0201L 2672,666 r180 top value=0
R33 "CRCW02010000Z0ED" 0201L 472.93,1701.52 r0 bottom value=0
R34 "CRCW040256K2FKED" 0402 2894.38,526 r180 bottom value=56.2k
R35 "CRCW02010000Z0ED" 0201L 2672,666 r180 bottom value=0
R36 "CRCW02010000Z0ED" 0201L 2672,642 r180 bottom value=0
R37 "CRCW040224K9FKED" 0402 3061.38,525.62 r180 bottom value=24.9k
R38 "CRCW02010000Z0ED" 0201L 2672,642 r180 top value=0
R39 "CRCW02010000Z0ED" 0201L 917,1459 r0 bottom value=0
R40 "CRCW040256K2FKED" 0402 2794,524 r270 bottom value=56.2k
R41 "CRCW02010000Z0ED" 0201L 817,1386.6 r270 top value=0
R42 "CRCW040224K9FKED" 0402 2738,524 r90 bottom value=24.9k
R43 "CRCW02010000Z0ED" 0201L 747,1385 r270 top value=0
R44 "RC0201FR-7D49R9L" 0201L 998.44,1378.65 r90 top value=49.9
R45 "RC0201FR-7D49R9L" 0201L 938.44,1378.65 r270 top value=49.9
R46 "RC0201FR-7D10RL" 0201L 736,1373 r0 top value=10.0
R47 "RC0201FR-7D10RL" 0201L 735,1341.27 r0 top value=10.0
R48 "RC0201FR-7D49R9L" 0201L 938.44,1340.65 r270 top value=49.9
R49 "CRCW02010000Z0ED" 0201L 747,1329 r90 top value=0
R50 "CRCW02010000Z0ED" 0201L 1657,1488 r180 bottom value=0
R51 "CRCW02010000Z0ED" 0201L 817,1330.22 r90 top value=0
R52 "CRCW02010000Z0ED" 0201L 999,1319.2 r90 top value=0
R53 "CRCW02010000Z0ED" 0201L 1714,1488.19 r180 bottom value=0
R54 "RC0201FR-7D4K7L" 0201 2283,790 r90 bottom value=4.70k
R55 "CRCW02010000Z0ED" 0201L 2374,448 r270 top value=0
R56 "RMCF0603ZT0R00" 0603 2106,852.62 r0 bottom value=0
R57 "RC0201FR-7D4K7L" 0201 2270,745 r0 bottom value=4.70k
R58 "RC0402FR-071KL" 0402 2317,831.38 r270 bottom value=1.00k
R59 "CRCW02010000Z0ED" 0201L 2394.47,448 r270 top value=0
R60 "CRCW02010000Z0ED" 0201L 2554.35,1033.02 r0 top value=0
R61 "RC0201FR-7D4K7L" 0201 2452,658 r270 bottom value=4.70k
R62 "CRCW02010000Z0ED" 0201L 2554.35,1013.02 r0 top value=0
R63 "RC0201FR-7D49R9L" 0201L 2520.87,417 r90 bottom value=49.9
R64 "RC0201FR-071KL" 0201L 2049,229 r90 bottom value=1.00k
R65 "RC0201FR-7D49R9L" 0201L 2532.5,458 r180 bottom value=49.9
R66 "CRCW02010000Z0ED" 0201L 2050,304 r180 bottom value=0
R67 "RC0201FR-071KL" 0201L 2049,173 r90 bottom value=1.00k
R68 "CRCW02010000Z0ED" 0201L 2405,486 r0 top value=0
R69 "RC0201FR-7D4K7L" 0201 2491,668.47 r0 bottom value=4.70k
R70 "RC0201FR-7D4K7L" 0201 2549,726 r0 bottom value=4.70k
R71 "RC0201FR-7D4K7L" 0201 2290,668 r0 top value=4.70k
R72 "RC0201FR-7D4K7L" 0201 2483,724 r0 bottom value=4.70k
R73 "CRCW02010000Z0ED" 0201L 1063.87,1333.62 r0 top value=0
R74 "CRCW02010000Z0ED" 0201L 1022.5,1233 r270 bottom value=0
R75 "CRCW02010000Z0ED" 0201L 1066,1576.98 r0 bottom value=0
R76 "ERJ-1GN0R00C" 0201L 1023.33,1543 r270 top value=0
R77 "ERJ-1GN0R00C" 0201 985.71,1494 r270 bottom value=0
R78 "CRCW0402499RFKED" 0402 1209.32,392.74 r90 bottom value=499
R79 "CRCW04020000Z0ED" 0402 1482.75,365.74 r0 bottom value=0
R80 "CRCW040259R0FKED" 0402 1403.75,393.24 r90 bottom value=59.0
R81 "CRCW040249R9FKED" 0402 1349.75,393.11 r90 bottom value=49.9
R82 "CRCW040237R4FKED" 0402 1175.87,653.74 r90 bottom value=37.4
R83 "CRCW04020000Z0ED" 0402 1390.32,661.74 r270 bottom value=0
R84 "CRCW0402200RFKED" 0402 1281.06,368.12 r180 bottom value=200
R85 "CRCW0402442RFKED" 0402 1154.87,912.84 r0 bottom value=442
R86 "CRCW0402200RFKED" 0402 1024.24,366 r0 bottom value=200
R87 "ERJ-2RKF4701X" 0402 1390.32,761.74 r270 bottom value=4.70k
R88 "CRCW040237R4FKED" 0402 1129.87,653.74 r90 bottom value=37.4
R89 "CRCW040259R0FKED" 0402 885.87,387.74 r270 bottom value=59.0
R90 "CRCW040249R9FKED" 0402 942.37,387.74 r270 bottom value=49.9
R91 "CRCW02010000Z0ED" 0201L 969.87,580.74 r180 bottom value=0
R92 "CRCW04020000Z0ED" 0402 809.37,361.74 r180 bottom value=0
R93 "CRCW02010000Z0ED" 0201L 1467.63,568.26 r270 bottom value=0
R94 "CRCW0402499RFKED" 0402 1097.67,393.74 r90 bottom value=499
R95 "CRCW0402499RFKED" 0402 1093.32,2348 r270 bottom value=499
R96 "CRCW04020000Z0ED" 0402 837.5,2324 r180 bottom value=0
R97 "CRCW040259R0FKED" 0402 955.8,2346.5 r270 bottom value=59.0
R98 "CRCW040249R9FKED" 0402 905.5,2346.5 r270 bottom value=49.9
R99 "CRCW040237R4FKED" 0402 1124.45,2085 r270 bottom value=37.4
R100 "CRCW04020000Z0ED" 0402 1045.9,2023 r180 bottom value=0
R101 "CRCW0402200RFKED" 0402 1028,2371 r0 bottom value=200
R102 "CRCW0402442RFKED" 0402 1152,1761 r180 bottom value=442
R103 "CRCW0402200RFKED" 0402 1269.5,2370.5 r180 bottom value=200
R104 "ERJ-2RKF4701X" 0402 1046.9,2074 r0 bottom value=4.70k
R105 "CRCW040237R4FKED" 0402 1174.9,2085 r270 bottom value=37.4
R106 "CRCW02010000Z0ED" 0201L 1291.38,2125 r270 bottom value=0
R107 "CRCW040259R0FKED" 0402 1388.5,2346 r90 bottom value=59.0
R108 "CRCW040249R9FKED" 0402 1337.5,2346 r90 bottom value=49.9
R109 "CRCW04020000Z0ED" 0402 1463.5,2322 r0 bottom value=0
R110 "CRCW02010000Z0ED" 0201L 761.5,2305.5 r270 bottom value=0
R111 "CRCW0402499RFKED" 0402 1204,2347 r270 bottom value=499
R112 "ERJ-L03KF50MV" 0603 778,1893.5 r90 bottom value=0.05
R113 "RC0402FR-071KL" 0402 2386,2597 r0 bottom value=1.00k
R114 "ERJ-L03KF50MV" 0603 1768.5,2079 r90 bottom value=0.05
R115 "Resistor" 0402 339,2334 r180 bottom value=0
R116 "Resistor" 0402 197,2138 r270 bottom value=0
R117 "Resistor" 0402 2015.66,2423.91 r180 bottom value=0
R118 "Resistor" 0402 1872,2613.5 r270 bottom value=0
R119 "Resistor" 0402 264,2310 r90 bottom value=0
R120 "Resistor" 0402 2017.51,2468.09 r180 bottom value=0
R121 "Resistor" 0402 263,2209 r90 bottom value=0
R122 "Resistor" 0402 2091.37,2489.91 r270 bottom value=0
R123 "RK73Z1ETTP" 0402 1723.5,573 r270 bottom value=0
R124 "RK73Z1ETTP" 0402 904,2229 r0 bottom value=0
R125 "RK73Z1ETTP" 0402 1808.78,257 r90 bottom value=0
R126 "RK73Z1ETTP" 0402 441.5,2298 r270 bottom value=0
R127 "RC0201FR-071KL" 0201L 1005.4,1583.02 r90 top value=1.00k
R128 "RC0201FR-07499RL" 0201L 956.5,1514.95 r180 top value=499
R129 "RC0201JR-072RL" 0201L 913.5,1525.98 r270 top value=2.0
R130 "CRCW02010000Z0ED" 0201L 926.5,1487.98 r0 top value=0
R131 "RC0201FR-079K76L" 0201L 841,1556.02 r0 top value=9.76k
R132 "RC0201FR-0714K3L" 0201L 842,1531 r0 top value=14.3k
R133 "CRCW02010000Z0ED" 0201L 1909,1733 r180 top value=0
R134 "CRCW02010000Z0ED" 0201L 1909,1771 r180 top value=0
R135 "CRCW02010000Z0ED" 0201L 2494,1837 r180 top value=0
R136 "CRCW02010000Z0ED" 0201L 2494,1882 r180 top value=0
R137 "CRCW02010000Z0ED" 0201L 1909,1810 r180 top value=0
R138 "RC0201FR-7D49R9L" 0201L 2814,1948 r270 bottom value=49.9
R139 "CRCW02010000Z0ED" 0201L 1909,1752 r180 top value=0
R140 "CRCW02010000Z0ED" 0201L 1909,1790 r180 top value=0
R141 "CRCW02010000Z0ED" 0201L 2494,1860 r180 top value=0
R142 "CRCW02010000Z0ED" 0201L 2494,1902 r180 top value=0
R143 "CRCW02010000Z0ED" 0201L 2561.99,1921.57 r180 bottom value=0
R144 "CRCW02010000Z0ED" 0201L 1909,1830 r180 top value=0
R145 "RK73H1ETTP10R0F" 0402 3038,2251 r270 top value=10.0
R146 "CRCW02010000Z0ED" 0201L 2424,1883 r180 bottom value=0
R147 "RC0201FS-7D10KL" 0201L 1835,1911 r0 top value=10.0k
R148 "RK73H1ETTP10R0F" 0402 2986,2250 r270 top value=10.0
R149 "CRCW02010000Z0ED" 0201L 2422,1947 r180 bottom value=0
R150 "CRCW02010000Z0ED" 0201L 1893,1911 r180 top value=0
R151 "CRCW02010000Z0ED" 0201L 1893,1888 r180 top value=0
R152 "RC0201FR-7D12KL" 0201L 2947,2180 r270 bottom value=12.0k
R153 "RC0201FS-7D1KL" 0201L 2851,2041 r90 bottom value=1.00k
R154 "CRCW04022K00JNED" 0402 2094,1777 r270 bottom value=2.0k
R155 "CRCW04022K00JNED" 0402 2146,1983 r270 bottom value=2.0k
R156 "CRCW02010000Z0ED" 0201L 2671.29,1896 r270 bottom value=0
R157 "CRCW02010000Z0ED" 0201L 2635,1895 r270 bottom value=0
R158 "RC0201FR-7D10KL" 0201L 2417,2386 r90 top value=10.0k
R159 "RC0201FR-7D10KL" 0201L 2387,2385.02 r90 top value=10.0k
R160 "RC0201FR-7D10KL" 0201L 2324,2379 r90 top value=10.0k
R161 "CRCW02010000Z0ED" 0201L 2598,1896 r270 bottom value=0
R162 "RC0201FR-7D2K2L" 0201L 2362,2385 r270 top value=2.20k
R163 "RC0201FR-7D10KL" 0201L 2588,1660 r90 bottom value=10.0k
R164 "RC0201FR-7D10KL" 0201L 2526,1660 r90 bottom value=10.0k
R165 "CRCW02010000Z0ED" 0201L 2618,1660 r90 bottom value=0
R166 "CRCW02010000Z0ED" 0201L 2754,1606 r180 bottom value=0
R167 "CRCW02010000Z0ED" 0201L 2526,1716.12 r90 bottom value=0
R168 "CRCW02010000Z0ED" 0201L 2480,1770.61 r180 bottom value=0
S1 "EVQ-5PN04K" SW_EVQ5PN04K 379,552 r270 top
T1 "ADT1-6T+" FP-ADT1-6T+_SMD6-MFG 1152.79,519.86 r0 top
T2 "ADT1-6T+" FP-ADT1-6T+_SMD6-MFG 1154.24,827.74 r180 top
T3 "ADT1-6T+" FP-ADT1-6T+_SMD6-MFG 1150.64,2220 r180 top
T4 "ADT1-6T+" FP-ADT1-6T+_SMD6-MFG 1150,1880.5 r0 top
T5 "ADT1-6T+" FP-ADT1-6T+_SMD6-MFG 531,1361 r270 top
TP1 "5011" Keystone5011 2217,855 r0 top
TP2 "5011" Keystone5011 873,974.8 r90 top
TP3 "5011" Keystone5011 147,623 r90 top
TP4 "5011" Keystone5011 501,1857.5 r90 top
TP5 "5011" Keystone5011 1554,802 r90 top
TP6 "5011" Keystone5011 649,671 r90 top
TP7 "5011" Keystone5011 1652,1718 r90 top
TP8 "5011" Keystone5011 810,1748 r90 top
TP9 "5011" Keystone5011 875,766 r0 top
TP10 "5011" Keystone5011 1554,629 r0 top
TP11 "5011" Keystone5011 1439,2005 r0 top
TP12 "5011" Keystone5011 653.5,2393.5 r0 top
U1 "SN65LVDS100DGKR" DGK0008A_L 2818,653.15 r180 bottom
U2 "HD3SS3411IRWAT" RWA0014A 1696.48,1390.04 r0 bottom
U3 "CDCE6214WRGERQ1" RGE0024P 2424,697 r90 top
U4 "ADC3683IRSBT" RSB0040B 1200.12,1374.54 r0 top
U5 "TPS3837E18DBVT" DBV0005A_N 563,482.85 r0 top
U6 "THS4541IRGTR" RGT0016A_NV 1152.79,521.86 r90 bottom
U7 "THS4541IRGTR" RGT0016A_NV 1149.84,2219 r270 bottom
U8 "INA226AIDGSR" DGS0010A_L 938,1864.76 r180 bottom
U9 "INA226AIDGSR" DGS0010A_L 1946,2109 r180 bottom
U10 "TPS62231TDRYRQ1" DRY0006A 148.5,2288.63 r0 bottom
U11 "TPS62231TDRYRQ1" DRY0006A 1981.5,2618.09 r180 bottom
U12 "LM7705MM/NOPB" DGK0008A_N 1918.78,443 r90 bottom
U13 "LM7705MM/NOPB" DGK0008A_N 609.5,2229 r0 bottom
U14 "TLV70233DBVR" DBV0005A_N 2287,2203 r270 bottom
U15 "OPA837IDBVR" DBV0006A_N 895,1627 r0 top
U16 "REF3318AIDCKR" DCK0003A_N 758,1621 r90 top
U17 "FT4232H-56Q-TRAY" VQFN-56 2602.02,2121 r180 bottom
U18 "LSF0204RUTR" RUT0012A 1824,1833.29 r0 top
U19 "SN74LVC1G125DCKT" DCK0005A_N 2399,1882 r180 top
U20 "SN74LV1T125DCKR" DCK0005A_N 2625.11,1743.62 r180 bottom
U21 "93LC46B-I/ST" TSSOP-8 2374,2179 r270 top
U22 "SN74LV1T125DCKR" DCK0005A_N 2809,1745 r0 bottom
U23 "SN74LV1T125DCKR" DCK0005A_N 2376,1745.02 r0 bottom
Y1 "KC3225A19.2000C3GE00" Kyocera_KC3225A 527.5,1606 r270 bottom
Y2 "ECS-100-12-33-AGN-TR" FP-ECS-100-12-33-AGN-TR_XTAL_SMD_3MM2_2MM5-MFG 2309.5,342.5 r270 top
Y3 "CVHD-957-10.000" FP-CVHD-957-10.000_SMT_XTAL_14MM2_9MM14-MFG 2301,303 r90 bottom
Y4 "ABM3-12.000MHZ-D2Y-T" XTAL_ABM3 2861,2192 r270 top
ZZ1 "This Assembly Note is for PCB labels only" AssemblyNoteLabel 57.28,5608 r0 top
ZZ2 "These assemblies are ESD sensitive, ESD precautions shall be observed." AssemblyNote 57.28,5508 r0 top
ZZ3 "These assemblies must be clean and free from flux and all contaminants. Use of no clean flux is not acceptable." AssemblyNote 56,5390 r0 top

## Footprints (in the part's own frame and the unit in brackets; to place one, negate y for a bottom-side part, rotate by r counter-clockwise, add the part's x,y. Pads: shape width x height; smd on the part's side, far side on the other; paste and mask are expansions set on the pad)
0201 [mm] "Data from Kemet datasheet CC101_COM dated 7/28/11"
  rect 0.46x0.42 smd mask+0.048: 1(-0.33,0) 2(0.33,0)
  body extent -0.31,-0.16 0.31,0.16, height 0.26
0201_033 [mm] "SMD, 2-Leads, Height 0.33mm"
  rect 0.46x0.42 smd mask+0.048: 1(-0.33,0) 2(0.33,0)
  body extent -0.31,-0.16 0.31,0.16, height 0.33
0201_033L [mm] "0201"
  rect 0.36x0.32 smd mask+0.048: 1(-0.28,0) 2(0.28,0)
  body extent -0.31,-0.16 0.31,0.16, height 0.33
0201L [mm] "Data from Kemet datasheet CC101_COM dated 7/28/11"
  rect 0.36x0.32 smd mask+0.048: 1(-0.28,0) 2(0.28,0)
  body extent -0.31,-0.16 0.31,0.16, height 0.26
0402 [mm] "0402 from SM-752 data"
  rect 0.8x0.6 smd: 1(-0.6,0) 2(0.6,0)
  silkscreen extent -1.22,-0.52 1.22,0.52, body extent -0.55,-0.3 0.55,0.3, height 0.6
0402_065 [mm] "0402"
  rect 0.8x0.6 smd: 1(-0.6,0) 2(0.6,0)
  silkscreen extent -1.22,-0.52 1.22,0.52, body extent -0.55,-0.3 0.55,0.3, height 0.65
0402L [mm] "0402 from SM-752 data"
  rect 0.6x0.5 smd: 1(-0.5,0) 2(0.5,0)
  body extent -0.55,-0.3 0.55,0.3, height 0.6
0603 [mm] "0603 from SM-752 data"
  rect 1x0.95 smd: 1(-0.8,0) 2(0.8,0)
  silkscreen extent -1.52,-0.69 1.52,0.69, body extent -0.87,-0.47 0.87,0.47, height 1
0603L [mm] "0603 from SM-752 data"
  rect 0.8x0.85 smd: 1(-0.7,0) 2(0.7,0)
  silkscreen extent -0.07,-0.33 0.07,0.33, body extent -0.87,-0.47 0.87,0.47, height 1
0805_HV [mil] "0805 with 30mil clearance between pads"
  rect 50x63 smd: 1(-40,0) 2(40,0)
  silkscreen extent -74,-40 74,40, body extent -43,-29 43,29, height 57
1206_190 [mm] "1206_190"
  rect 1.1x1.6 smd: 1(-1.7,0) 2(1.7,0)
  silkscreen extent -0.9,-1 0.9,1, body extent -1.75,-0.95 1.75,0.95, height 1.9
1210_270 [mm] "1210"
  rect 1.3x2.7 smd: 1(-1.45,0) 2(1.45,0)
  silkscreen extent -2.32,-1.57 2.32,1.57, body extent -1.7,-1.35 1.7,1.35, height 2.7
AMPHENOL_901-144-8RFX [mm] "SMA Straight Jack, TH"
  round 2 hole 1.5: 1(0,0)
  round 2.2 hole 1.7: 2(-2.54,2.54) 3(-2.54,-2.54) 4(2.54,-2.54) 5(2.54,2.54)
  silkscreen extent -3.7,-3.7 3.7,3.7, body extent -3.7,-3.7 3.7,3.7, height 9.93
AssemblyNote [mil] "Assembly Note"
AssemblyNoteLabel [mil] "Assembly Note for PCB Labels"
CE_Mark_5mm [mil] "Minimum text height for CE Mark"
  silkscreen extent -138,-98 138,98
CONN_USB-Mini-B-1734035-2 [mm] "Tyco Connectivity recommended land pattern"
  rect 0.5x2.3 smd: 1(-1.6,2.6) 2(-0.8,2.6) 3(0,2.6) 4(0.8,2.6) 5(1.6,2.6)
  rect 2x2.5 smd: 6(4.45,2.5) 7(4.45,-3) 8(-4.45,-3) 9(-4.45,2.5)
  round 0.9 hole 0.9 unplated: 10(2.2,0) 11(-2.2,0)
  silkscreen extent -5,-5 4.9,4.19, body extent -4.95,-5.9 4.95,3.3, height 4.1
DBV0005A_N [mm] "SOT23, 5-Leads, Body 2.9x1.6mm, Pitch 0.95mm, Lead Span 2.8mm, IPC Medium Density"
  rrect17% 1x0.6 smd: 1(-1.375,0.95) 2(-1.375,0) 3(-1.375,-0.95) 4(1.375,-0.95) 5(1.375,0.95)
  silkscreen extent -1.63,-1.55 0.38,1.55, body extent -1.42,-1.46 1.42,1.46, height 1.09
DBV0006A_N [mm] "SOT23, 6-Leads, Body 2.9x1.6mm, Pitch 0.95mm, Lead Span 2.8mm, IPC Medium Density"
  rrect17% 1x0.6 smd: 1(-1.375,0.95) 2(-1.375,0) 3(-1.375,-0.95) 4(1.375,-0.95) 5(1.375,0) 6(1.375,0.95)
  silkscreen extent -1.68,-1.55 0.5,1.55, body extent -1.42,-1.46 1.42,1.46, height 1.12
DCK0003A_N [mm] "SOT23, 3-Leads, Body 2.0x1.25mm, Pitch 0.65mm, Lead Span 2.1mm, IPC Medium Density"
  rrect25% 0.85x0.4 smd: 1(-1.125,0.65) 2(-1.125,-0.65) 3(1.125,0)
  silkscreen extent -1.02,-1.1 0.7,1.52, body extent -1.06,-1 1.06,1, height 1.1
DCK0005A_N [mm] "SOT353, 5-Leads, Body 2x1.3mm, Pitch 0.65mm, Lead Span 2.1mm, IPC Medium Density"
  rrect25% 0.85x0.4 smd: 1(-1.125,0.65) 2(-1.125,0) 3(-1.125,-0.65) 4(1.125,-0.65) 5(1.125,0.65)
  silkscreen extent -1.48,-1.02 0.55,1.1, body extent -1.14,-1 1.14,1, height 0.95
DGK0008A_L [mm] "TSOP, 8-Leads, Body 3x3mm, Pitch 0.65mm, IPC High Density"
  oval 1.15x0.45 smd: 1(-2.125,0.975) 2(-2.125,0.325) 3(-2.125,-0.325) 4(-2.125,-0.975) 5(2.125,-0.975) 6(2.125,-0.325) 7(2.125,0.325) 8(2.125,0.975)
  silkscreen extent -2.58,-1.55 0.95,1.55, body extent -2.45,-1.5 2.45,1.5, height 0.96
DGK0008A_N [mm] "TSOP, 8-Leads, Body 3x3mm, Pitch 0.65mm, IPC Medium Density"
  oval 1.35x0.45 smd: 1(-2.225,0.975) 2(-2.225,0.325) 3(-2.225,-0.325) 4(-2.225,-0.975) 5(2.225,-0.975) 6(2.225,-0.325) 7(2.225,0.325) 8(2.225,0.975)
  silkscreen extent -2.75,-1.55 0.95,1.55, body extent -2.45,-1.5 2.45,1.5, height 0.96
DGS0010A_L [mm] "TSSOP, 10-Leads, Body 3x3mm, Pitch 0.5mm, IPC High Density"
  oval 1.15x0.25 smd: 1(-2.125,1) 2(-2.125,0.5) 3(-2.125,0) 4(-2.125,-0.5) 5(-2.125,-1) 6(2.125,-1) 7(2.125,-0.5) 8(2.125,0) 9(2.125,0.5) 10(2.125,1)
  silkscreen extent -2.65,-1.55 0.9,1.55, body extent -2.45,-1.5 2.45,1.5, height 0.96
DRY0006A [mm] "USON-6"
  rrect67% 0.45x0.3 smd paste-0.05 mask-0.05: 1(-0.275,0.5)
  rrect67% 0.4x0.3 smd paste-0.05 mask-0.05: 2(-0.3,0) 3(-0.3,-0.5) 4(0.3,-0.5) 5(0.3,0) 6(0.3,0.5)
  body extent -0.5,-0.72 0.5,0.72, height 0.58
FCC_disclaimer [mil]
Fiducial10-20 [mm]
  round 1 smd mask+0.5: 1(0,0)
  L1_Top Layer keep-out circle w1.178: c0,0 r0.5
FP-ADT1-6T+_SMD6-MFG [mil]
  rrect6% 65x100 smd paste+0 mask+0: 1(-100,-100) 2(0,-100) 3(100,-100) 4(100,100) 5(0,100) 6(-100,100)
  silkscreen extent -169,-151 158,112, body extent -161,-154 161,154, height 10
FP-CVHD-957-10.000_SMT_XTAL_14MM2_9MM14-MFG [mm]
  rrect8% 1.27x2.28 smd paste+0 mask+0: 1(-2.54,-3.555) 2(0,-3.555) 3(2.54,-3.555) 4(2.54,3.555) 5(0,3.555) 6(-2.54,3.555)
  silkscreen extent -7.1,-5.57 7.1,4.57, body extent -7.1,-4.57 7.1,4.57, height 5.3
FP-ECS-100-12-33-AGN-TR_XTAL_SMD_3MM2_2MM5-MFG [mm]
  rrect9% 1.3x1.1 smd paste+0 mask+0: 1(-1.15,-0.9) 2(1.15,-0.9) 3(1.15,0.9) 4(-1.15,0.9)
  silkscreen extent -2.52,-1.3 0.13,1.3, body extent -1.6,-1.25 1.6,1.25, height 0.8
IND_LQG15H [mm] "MuRata"
  rect 0.55x0.6 smd: 1(-0.475,0) 2(0.475,0)
  body extent -0.52,-0.27 0.52,0.27, height 0.55
Johnson_142-0701-801#1 [mil] "Johnson Components recommended land pattern"
  rect 90x200 smd: 1(0,0)
  rect 95x200 smd: 2(-172.5,0) 3(172.5,0)
  round 38 hole 18: 2(-172.5,-135) 3(172.5,-135)
  rect 95x200 smd far side: 4(-172.5,0) 5(172.5,0)
  L1_Top Layer lines w18: 172.5,0 172.5,-135 ; -172.5,0 -172.5,-135
  L6_Bottom Layer lines w18: 172.5,0 172.5,-135 ; -172.5,0 -172.5,-135
  silkscreen extent -235,-170 235,100, body extent -190,-92 190,480, height 165
Johnson_142-0701-801#2 [mil] "Johnson Components recommended land pattern"
  rect 90x200 smd: 1(0,0)
  round 38 hole 18: 2(-172.5,-135) 3(172.5,-135)
  rect 95x200 smd: 2(-172.5,0) 3(172.5,0)
  rect 95x200 smd far side: 4(-172.5,0) 5(172.5,0)
  L1_Top Layer lines w18: -172.5,0 -172.5,-135 ; 172.5,0 172.5,-135
  L6_Bottom Layer lines w18: -172.5,0 -172.5,-135 ; 172.5,0 172.5,-107 172.5,-135
  silkscreen extent -235,-170 235,100, body extent -190,-92 190,480, height 165
Keystone5011 [mil] "Keystone Multipurpose loops"
  round 87 hole 63: 1(0,0)
  silkscreen extent -70,-70 70,70, body extent -63,-63 63,62, height 319
Keystone_1902E [mil] "Hex Standoff, 4-40 threaded, nylon"
  round 1 on Mech4: 0(0,0)
  body extent -145,-126 146,126, height 1001
Kyocera_KC3225A [mm] "SMD, 4-Leads, Body 3.2x2.5mm"
  rrect11% 0.95x1.2 smd: 1(-0.875,1.1) 2(-0.875,-1.1) 3(0.875,-1.1) 4(0.875,1.1)
  silkscreen extent -1.7,-2.05 1.7,2.05, body extent -1.25,-1.6 1.25,1.6, height 1.01
Label_650x200 [mil] "Thermal Transfer Label"
  round 1 on Mech13: 0(0,0)
  silkscreen extent -325,-100 325,100, body extent -325,-100 325,100, height 1
LQG15WZ_02 [mm] "MuRata recommended land pattern"
  rrect29% 0.35x0.65 smd: 1(-0.425,0) 2(0.425,0)
  body extent -0.52,-0.32 0.52,0.32, height 0.6
LTST-C150_1206_Green [mm] "SMD, 2-Leads, Body 1.6x3.2mm"
  rect 1.5x1.5 smd: 1(-1.75,0) 2(1.75,0)
  silkscreen extent -3.3,-1.15 2.65,1.15, body extent -1.65,-0.85 1.65,0.85, height 1.2
Murata_NFM31P [mm] "SMD, 3-Leads, Body 3.2x1.6mm"
  rect 0.95x1 smd paste-2 mask-2: 1(-1.725,0) 3(1.725,0)
  rect 1x0.7 smd paste-2 mask+0: 2(0,-0.65) 2(0,0.65)
  silkscreen extent -2.59,-1.2 2.59,1.2, body extent -1.7,-0.9 1.7,0.9, height 1.5
"NY PMS 440 0025 PH" [mm] "4-40 nylon screw and mounting hole"
  round 8 hole 3.2: 1(0,0)
  body extent -3.3,-3.3 3.3,3.3, height 2.69
RGE0024P [mm] "VQFN-24"
  rrect40% 0.6x0.25 smd: 1(-1.9,1.25) 2(-1.9,0.75) 3(-1.9,0.25) 4(-1.9,-0.25) 5(-1.9,-0.75) 6(-1.9,-1.25) 13(1.9,-1.25) 14(1.9,-0.75) 15(1.9,-0.25) 16(1.9,0.25) 17(1.9,0.75) 18(1.9,1.25)
  rrect40% 0.25x0.6 smd: 7(-1.25,-1.9) 8(-0.75,-1.9) 9(-0.25,-1.9) 10(0.25,-1.9) 11(0.75,-1.9) 12(1.25,-1.9) 19(1.25,1.9) 20(0.75,1.9) 21(0.25,1.9) 22(-0.25,1.9) 23(-0.75,1.9) 24(-1.25,1.9)
  rrect4% 2.7x2.7 smd paste-2.7: 25(0,0)
  rrect40% 0.25x0.25 smd: A1(-1.75,1.75) A2(-1.75,-1.75) A3(1.75,-1.75) A4(1.75,1.75)
  body extent -2,-2 2,2, height 0.9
